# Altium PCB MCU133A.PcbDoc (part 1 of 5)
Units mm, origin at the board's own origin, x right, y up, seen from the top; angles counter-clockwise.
Board outline 58.42 x 139.7 mm, 4 copper layers (Top Signal, GND, PWR, Bottom Signal), stack 1.565 mm thick; 278 components, 226 nets, 1057 pads, 868 vias.
Unrouted connection lines stored in the file: 237.
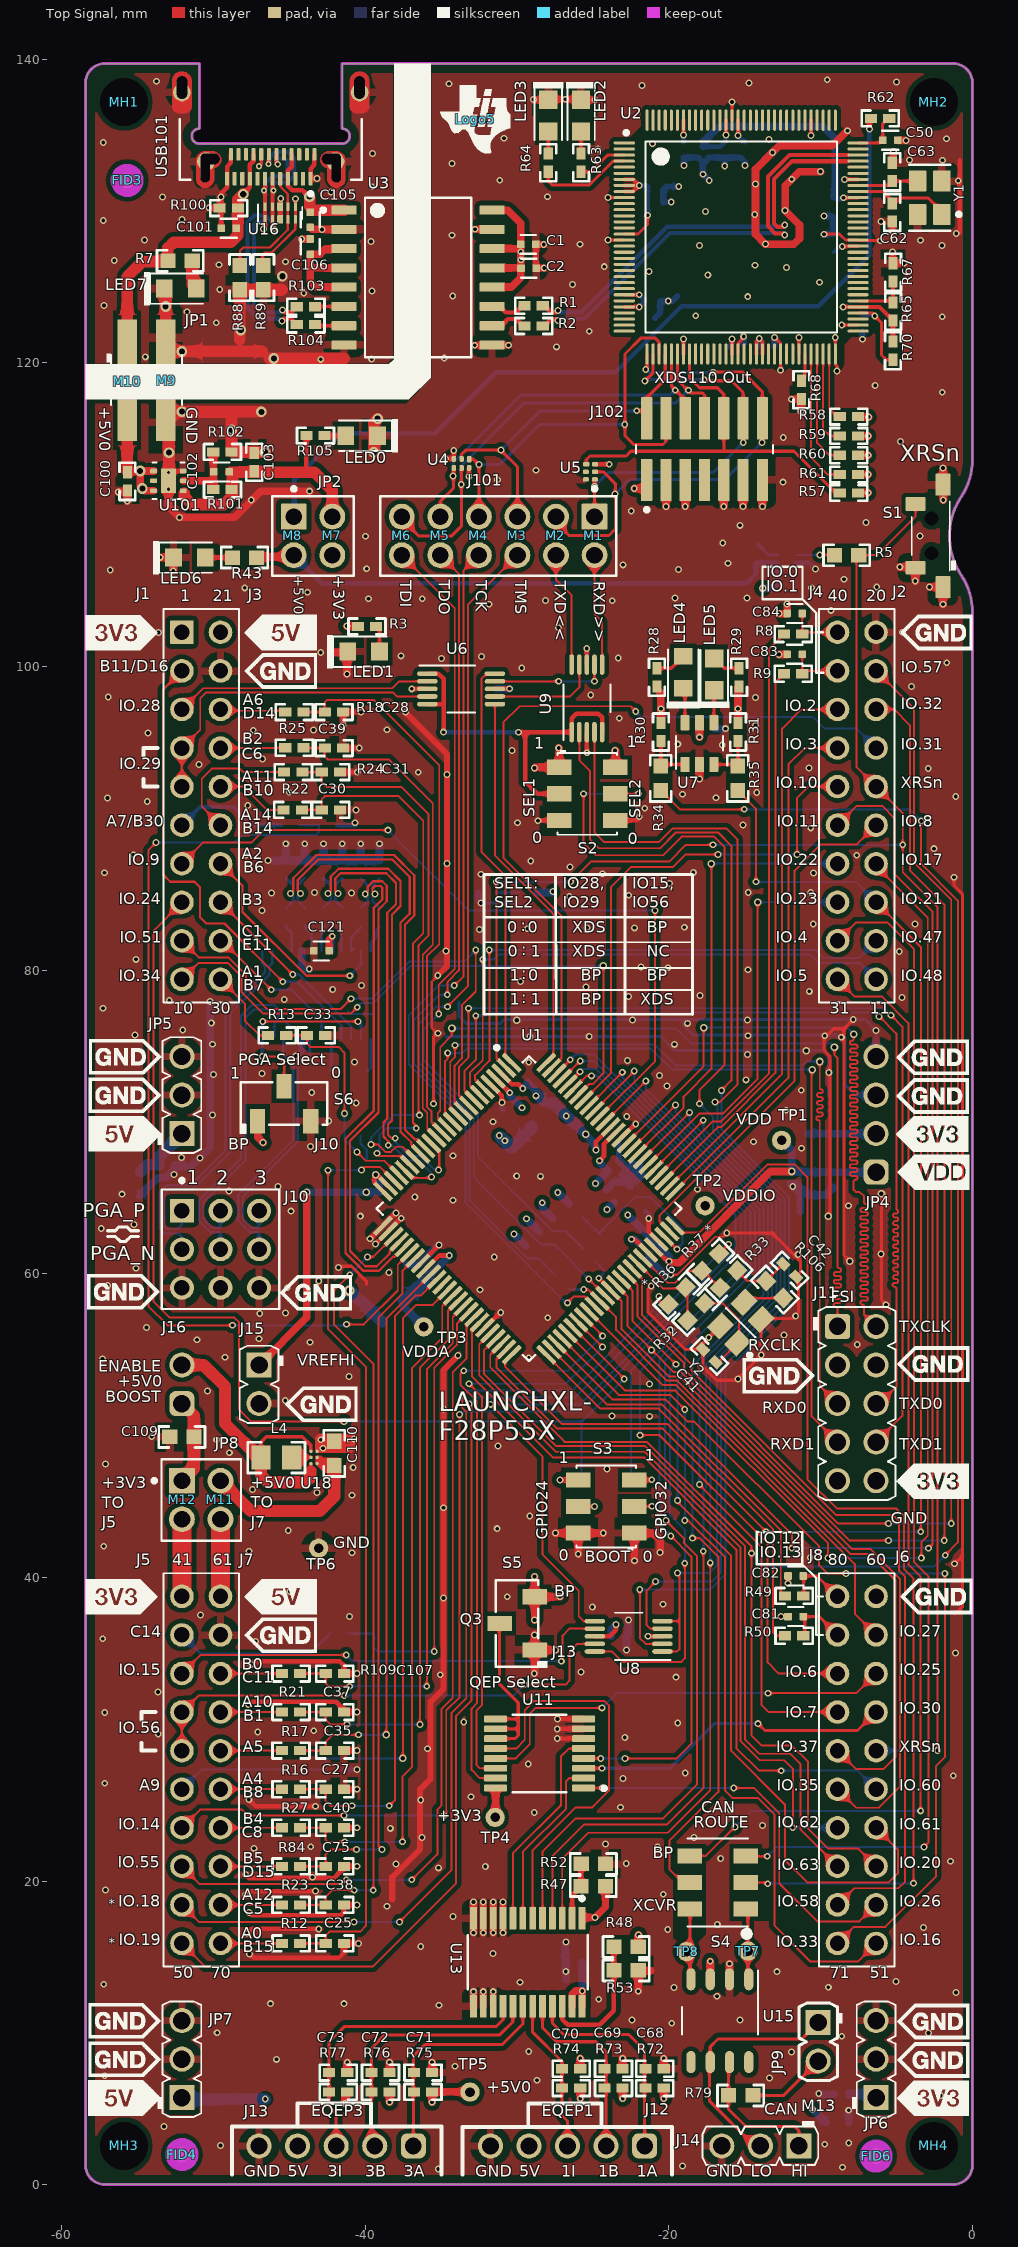
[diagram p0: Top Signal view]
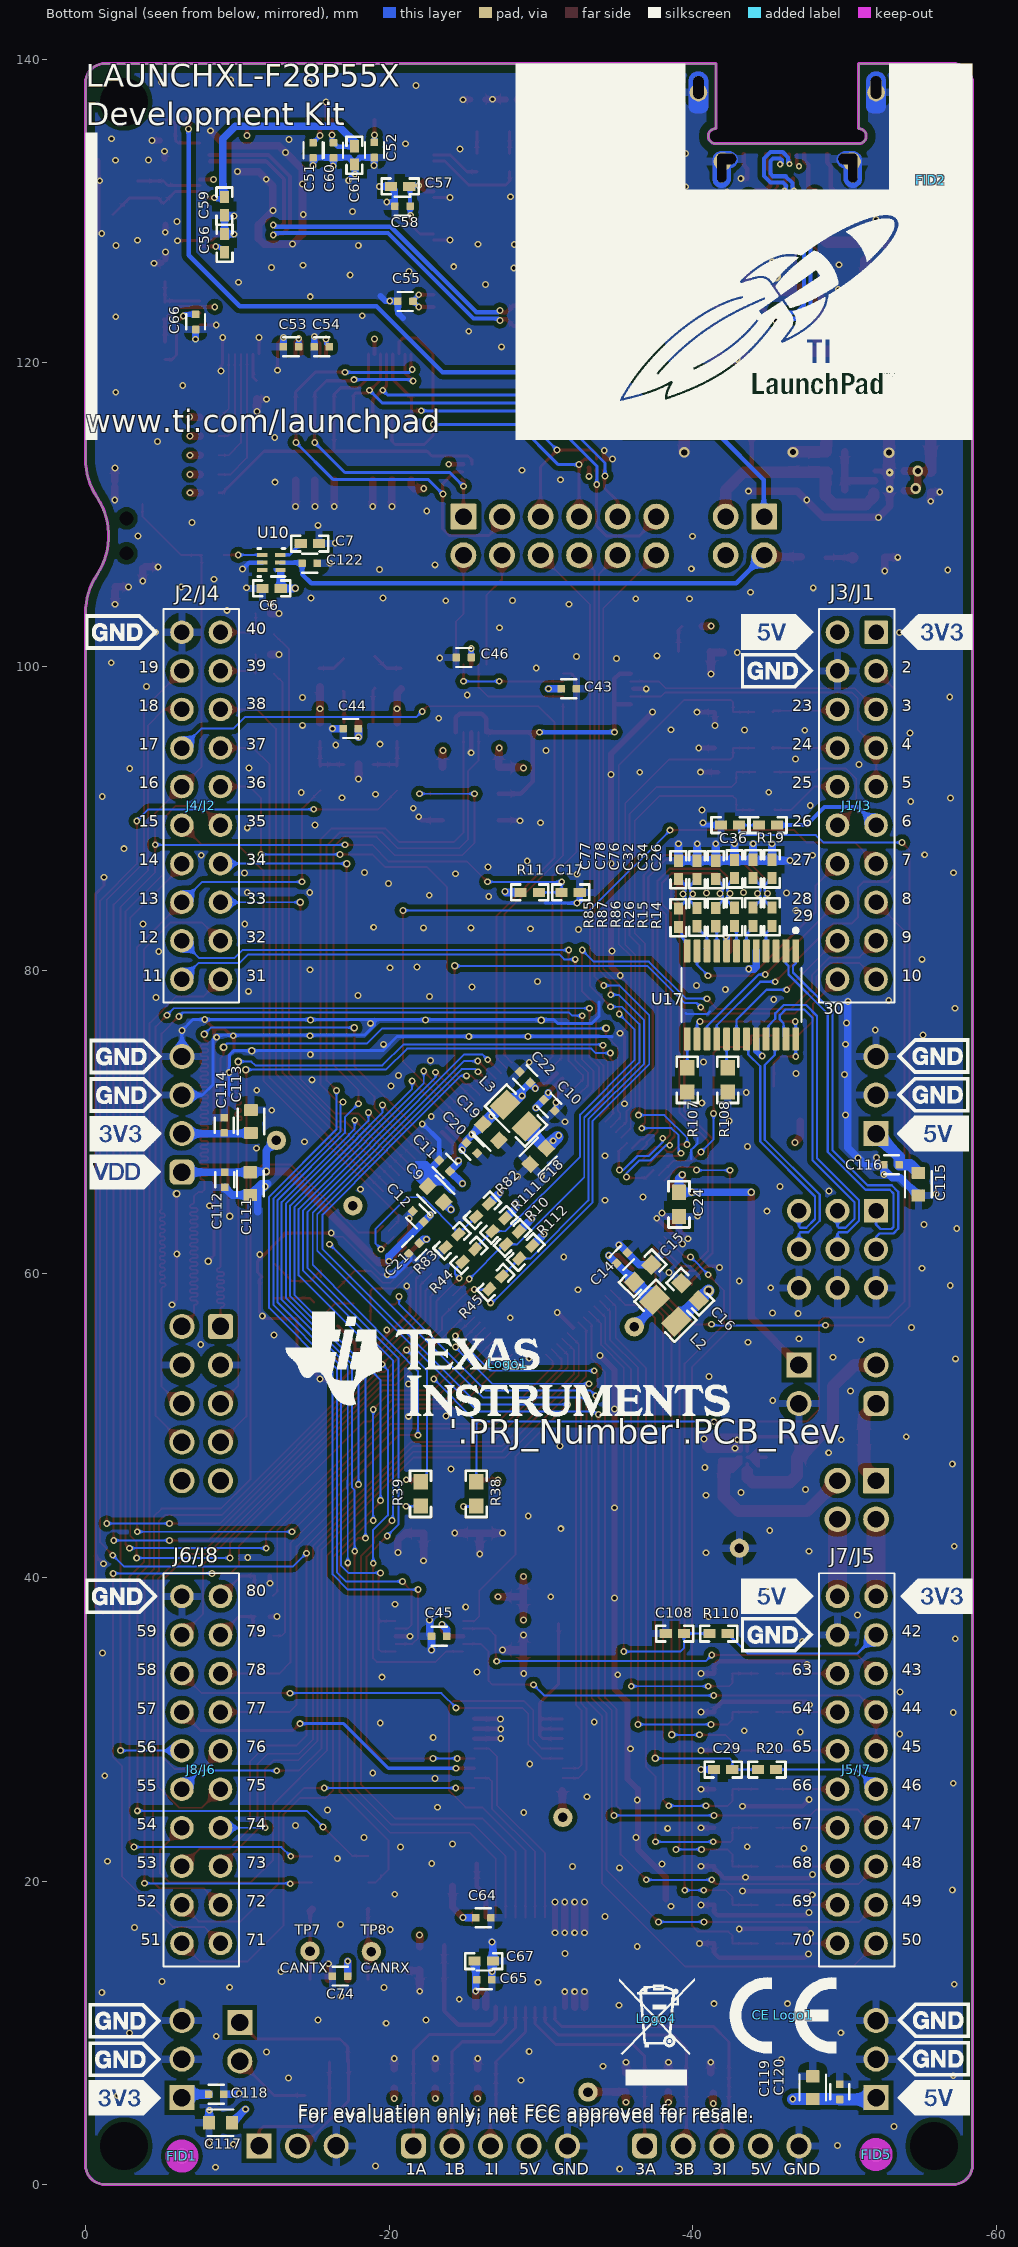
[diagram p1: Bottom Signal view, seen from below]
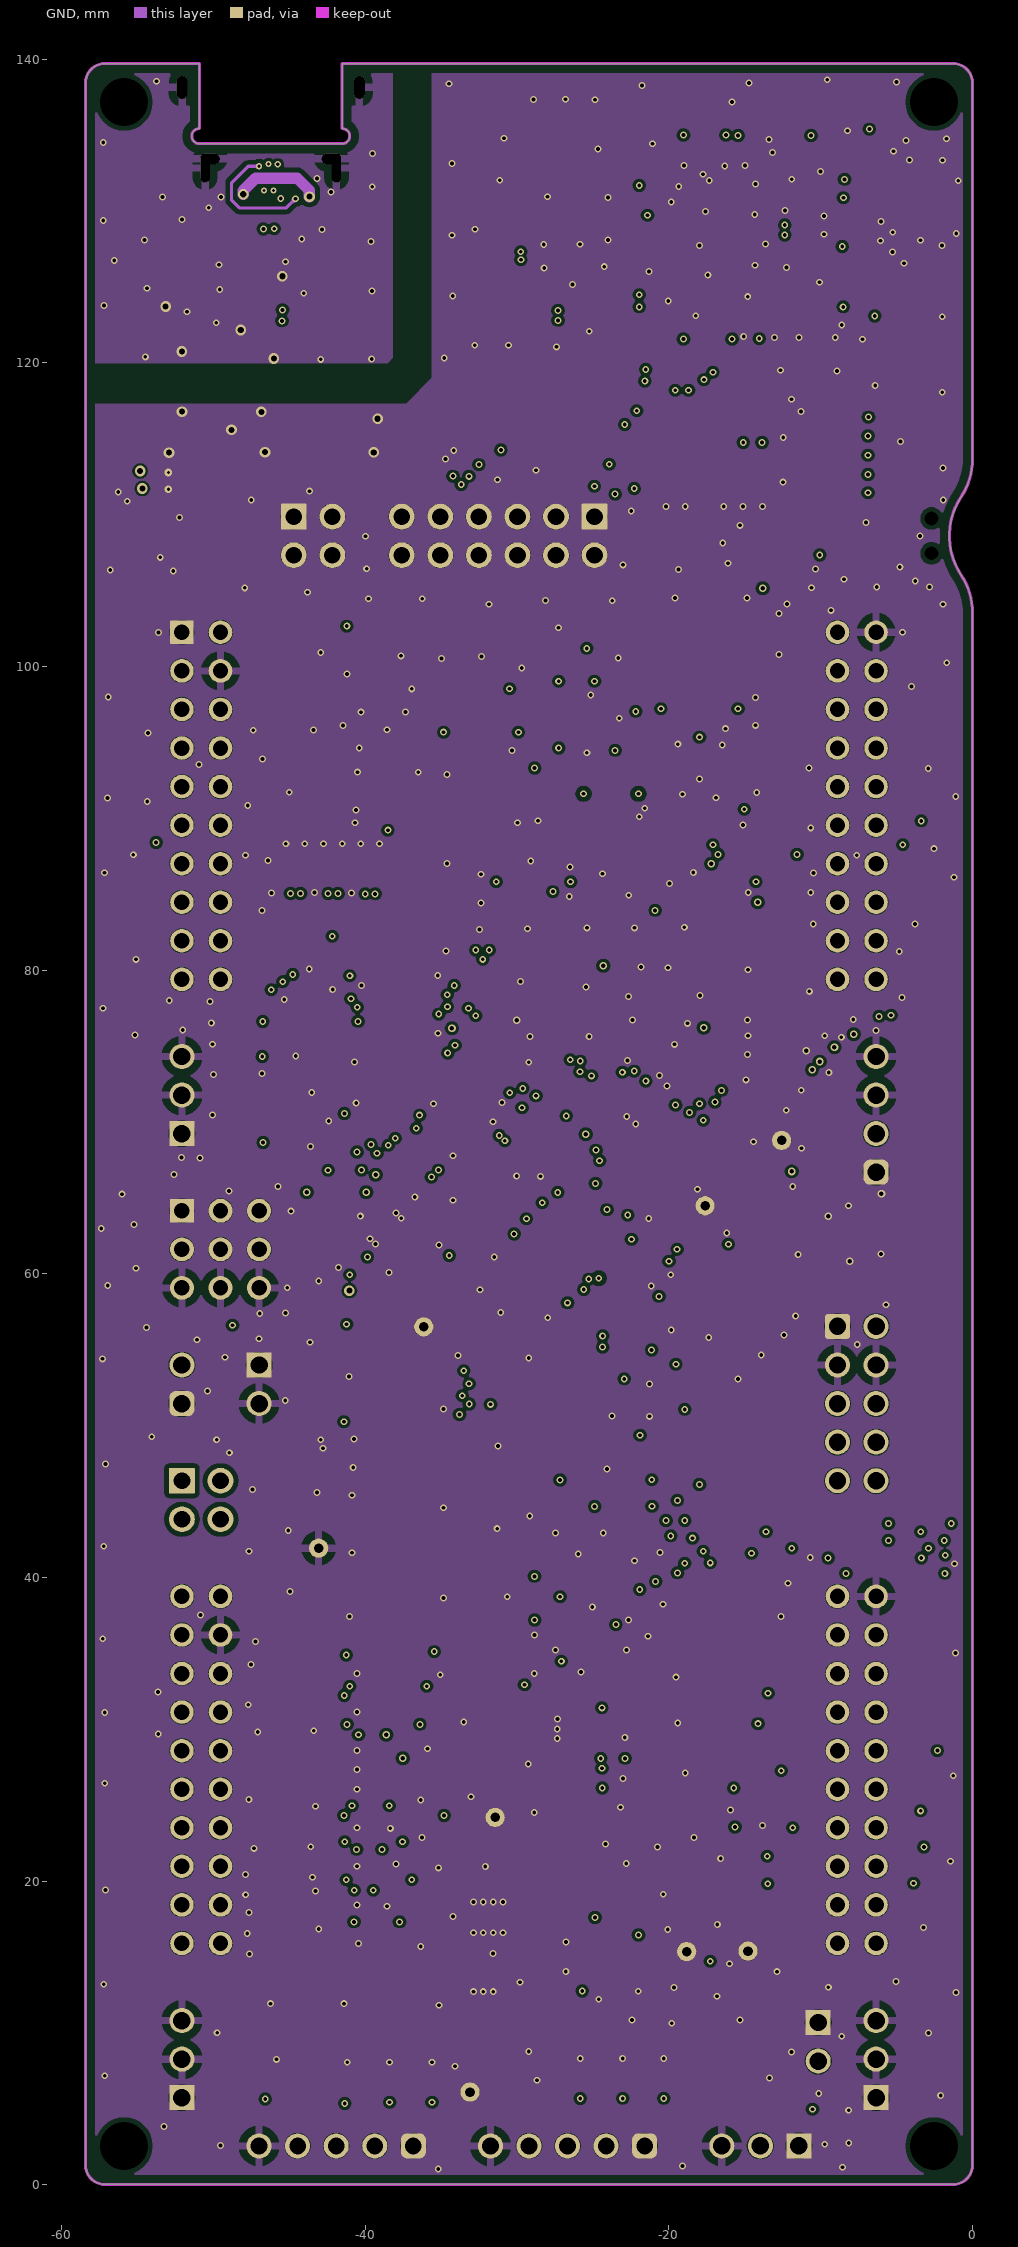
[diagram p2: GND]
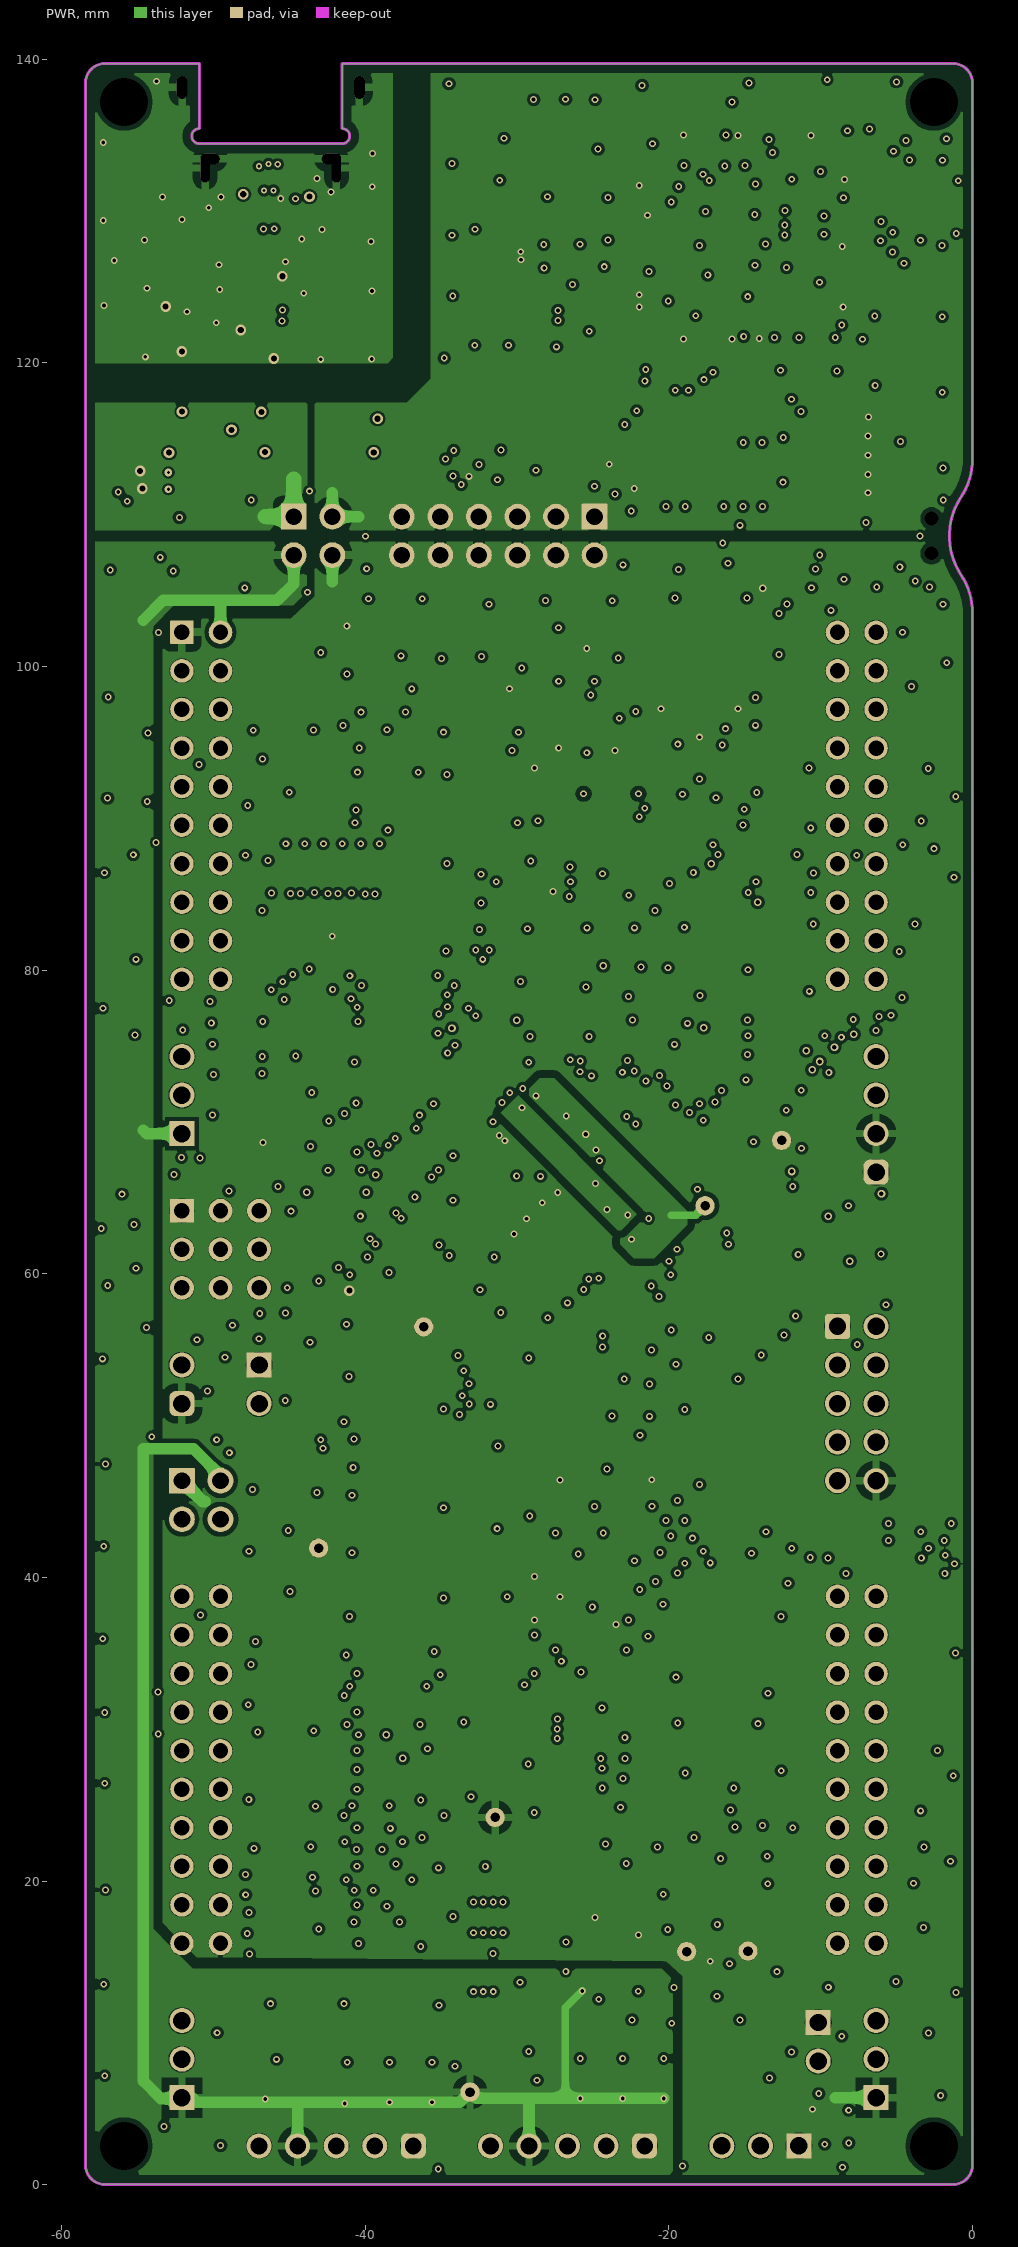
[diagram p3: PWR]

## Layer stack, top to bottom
Top Solder: solder mask 0.0102, Solder Resist, Dk 3.5
Top Signal: signal copper 0.0356
Dielectric 1: prepreg 0.2032, FR-4, Dk 4.2
GND: signal copper 0.0356
Dielectric 2: core 1.016, FR-4, Dk 4.2
PWR: signal copper 0.0356
Dielectric 3: prepreg 0.2032, FR-4, Dk 4.2
Bottom Signal: signal copper 0.0356
Bottom Solder: solder mask 0.0102, Solder Resist, Dk 3.5

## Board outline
-57.151,0.014 cw(c-57.151,1.284) -58.421,1.284 -58.421,138.444 cw(c-57.151,138.444) -57.151,139.714 -50.921,139.714 -50.921,135.434 ccw(c-50.921,134.934) -51.421,134.934 ccw(c-50.921,134.934) -50.921,134.434 -41.521,134.434 ccw(c-41.521,134.934) -41.021,134.934 ccw(c-41.521,134.934) -41.521,135.434 -41.521,139.714 -1.271,139.714 cw(c-1.271,138.444) -0.001,138.444 -0.001,113.679 cw(c-4.615,113.679) -0.763,111.139 ccw(c3.089,108.599) -0.763,106.059 cw(c-4.615,103.519) -0.001,103.519 -0.001,1.284 cw(c-1.271,1.284) -1.271,0.014

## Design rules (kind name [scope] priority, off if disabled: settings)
AcuteAngle [All] p1: minimum=4.50000000000000E+0001 checktracksonly=TRUE
AssemblyTestPointUsage [All] p1: valid=2
BoardOutlineClearance BoardOutlineClearance_MountingHoles [OnCopper and InComponentClass('Mounting Holes')] p1: gap=1.016 ignorepadtopadclearanceinfootprint=FALSE
BoardOutlineClearance BoardOutlineClearance_Poly [OnCopper and IsPoly] p2: gap=0.635 ignorepadtopadclearanceinfootprint=FALSE
BoardOutlineClearance BoardOutlineClearance_USB101 [InComponent('USB101')] p3: gap=0 ignorepadtopadclearanceinfootprint=FALSE
BoardOutlineClearance [OnCopper and Not InComponentClass('Logo') and not InComponentClass('FiducialMark') and not InRegion(1000,500,4000,800) and not InPoly] p4: gap=0.254 ignorepadtopadclearanceinfootprint=FALSE
Clearance USB101 [InComponent('USB101') vs OnLayer('Keep-Out Layer')] p1: gap=0.2 ignorepadtopadclearanceinfootprint=FALSE
Clearance Clearance_1 [inpolygon vs inpolygon] p2: gap=0.5 ignorepadtopadclearanceinfootprint=FALSE
Clearance ISVIA [ISVIA vs ISVIA] p3: gap=0.2 ignorepadtopadclearanceinfootprint=FALSE
Clearance Clearance_FiducialMark [InComponentClass('FiducialMark') vs InComponentClass('FiducialMark')] p4: gap=0 ignorepadtopadclearanceinfootprint=FALSE
Clearance Clearance_Boardedge [All vs IsKeepOut] p5: gap=0.3 ignorepadtopadclearanceinfootprint=FALSE
Clearance INPOLYGON [InPolygon] p6: gap=0.3 ignorepadtopadclearanceinfootprint=FALSE
Clearance [All] p7: gap=0.15 ignorepadtopadclearanceinfootprint=FALSE
ComponentClearance ComponentClearance_THtoTH_1 [All vs InComponentClass('Shunt')] p1: gap=0 collisioncheckmode=3 verticalgap=0 showdistances=FALSE
ComponentClearance "ComponentClearance_overlay to overlay" [OnBottomSilkscreen vs OnTopSilkscreen] p2: gap=0 collisioncheckmode=3 verticalgap=0 showdistances=FALSE
ComponentClearance ComponentClearance_MountingHoles_FiducialMarks [InComponentClass('Mounting Holes') vs InComponentClass('FiducialMark')] p3: gap=1.27 collisioncheckmode=3 verticalgap=0.254 showdistances=FALSE
ComponentClearance ComponentClearance_Shunt [InComponentClass('Header') vs InComponentClass('Shunt')] p4: gap=0 collisioncheckmode=3 verticalgap=0 showdistances=FALSE
ComponentClearance ComponentClearance_Logo [InComponentClass('Logo')] p5: gap=0 collisioncheckmode=3 verticalgap=0 showdistances=FALSE
ComponentClearance ComponentClearance_Logo_1 [InComponentClass('Logo') vs InComponentClass('Logo')] p6: gap=0 collisioncheckmode=3 verticalgap=0 showdistances=FALSE
ComponentClearance ComponentClearance_ScrewToNut [(HasFootprint('NY PMS 440 0025 PH')) vs (HasFootprint('Keystone_1902C'))] p7: gap=0.1 collisioncheckmode=3 verticalgap=0.1 showdistances=FALSE
ComponentClearance ComponentClearance_MountingHoles [InComponentClass('Mounting Holes')] p8: gap=6.35 collisioncheckmode=3 verticalgap=2540 showdistances=FALSE
ComponentClearance ComponentClearance_SmallPassives [HasFootprint('0201*') or HasFootprint('0402*') or HasFootprint('0508') or HasFootprint('0603*') or HasFootprint('0612') or HasFootprint('0805*') or HasFootprint('0815*') or HasFootprint('0830*') or HasFootprint('1206*') or HasFootprint('1210*') or HasFootprint('1808*') or HasFootprint('1812*') or HasFootprint('1825*') or HasFootprint('2010*') or HasFootprint('2220*') or HasFootprint('2225*') or HasFootprint('2512*') or HasFootprint('2728*') or HasFootprint('3518*') vs HasFootprint('0201*') or HasFootprint('0402*') or HasFootprint('0508') or HasFootprint('0603*') or HasFootprint('0612') or HasFootprint('0805*') or HasFootprint('0815*') or HasFootprint('0830*') or HasFootprint('1206*') or HasFootprint('1210*') or HasFootprint('1808*') or HasFootprint('1812*') or HasFootprint('1825*') or HasFootprint('2010*') or HasFootprint('2220*') or HasFootprint('2225*') or HasFootprint('2512*') or HasFootprint('2728*') or HasFootprint('3518*')] p9: gap=0.254 collisioncheckmode=3 verticalgap=0 showdistances=FALSE
ComponentClearance ComponentClearance_THtoSMT [IsThruComponent vs IsSMTComponent] p10: gap=0.254 collisioncheckmode=3 verticalgap=0.254 showdistances=FALSE
ComponentClearance ComponentClearance_THtoTH [IsThruComponent vs IsThruComponent] p11: gap=0.508 collisioncheckmode=3 verticalgap=0.762 showdistances=FALSE
DiffPairsRouting [All] p1: maxlimit=2.54 minlimit=0.15 mostfreqgap=0.15 toplayer_minwidth=0.15 toplayer_maxwidth=0.381 toplayer_prefwidth=0.27 midlayer1_minwidth=0.15 midlayer1_maxwidth=0.381 midlayer1_prefwidth=0.27 midlayer2_minwidth=0.15 midlayer2_maxwidth=0.381 midlayer2_prefwidth=0.27 bottomlayer_minwidth=0.15 bottomlayer_maxwidth=0.381 bottomlayer_prefwidth=0.27 maxuncoupledlength=25.4
FabricationTestPointUsage TestPointUsage [All] p1: valid=2 allowmultiple=FALSE
FabricationTestpoint Testpoint [All] p1: side=3 testpointundercomponent=TRUE minsize=1.016 maxsize=2.54 preferedsize=1.524 minholesize=0 maxholesize=1.016 preferedholesize=0.813 testpointgrid=0.025 allowsidetop=TRUE allowsidebottom=TRUE usegrid=TRUE gridtolerance=0
FanoutControl Fanout_LCC [IsLCC] p1: bgadir=Out bgaviamode=Centered fanoutstyle=Auto fanoutdirection=Alternating viagrid=0.025 // Fanout_LCC (Default Rule)
FanoutControl Fanout_BGA [IsBGA] p2: bgadir=Out bgaviamode=Centered fanoutstyle=Auto fanoutdirection=Alternating viagrid=0.025 // Fanout_BGA (Default Rule)
FanoutControl Fanout_Default [All] p4: bgadir=Out bgaviamode=Centered fanoutstyle=Auto fanoutdirection=Alternating viagrid=0.025 // Fanout_Default (Default Rule)
FanoutControl Fanout_Small [(CompPinCount < 5)] p5: bgadir=Out bgaviamode=Centered fanoutstyle=Auto fanoutdirection=OutThenIn viagrid=0.025 // Fanout_Small (Default Rule)
HoleSize [All] p1: absolutevalues=TRUE maxlimit=6.375 minlimit=0.2 maxpercent=80.000 minpercent=20.000
HoleToHoleClearance HoleToHoleClearance_USB101 [InComponent('USB101') vs InComponent('USB101')] p1: gap=0 allowstackedmicrovias=TRUE
HoleToHoleClearance [All] p2: gap=0.25 allowstackedmicrovias=TRUE
MatchedLengths FSIRX [InNetClass('FSIRX')] p1: tolerance=0.635 checknetsindiffpair=FALSE checkdiffpairvsdiffpair=TRUE checkxsignals=TRUE checkothers=TRUE
MatchedLengths FSITX [InNetClass('FSITX')] p2: tolerance=0.635 checknetsindiffpair=FALSE checkdiffpairvsdiffpair=TRUE checkxsignals=TRUE checkothers=TRUE
MinimumAnnularRing MinimumAnnularRing_1 [InComponent('USB101')] p1: minimumring=0
MinimumAnnularRing [All] p2: minimumring=0.1
MinimumAnnularRing MinimumAnnularRing_ThermalPadVias [IsVia and InAnyComponent] p3: minimumring=0.1
MinimumSolderMaskSliver MinimumSolderMaskSliver_Logo [InComponentClass('Logo') vs InComponentClass('Logo')] p1: minsoldermaskwidth=0.018
MinimumSolderMaskSliver [All] p2: minsoldermaskwidth=0.076
PlaneClearance [All] p1: clearance=0.127
PlaneConnect [All] p1: planeconnectstyle=Relief reliefexpansion=0.254 reliefentries=4 reliefconductorwidth=0.635 reliefairgap=0.254
PolygonConnect PolygonConnect_via [isvia] p1: connectstyle=Direct reliefconductorwidth=0.254 reliefentries=4 polygonreliefangle="90 Angle" airgapwidth=0.127
PolygonConnect [All] p2: connectstyle=Relief reliefconductorwidth=0.508 reliefentries=4 polygonreliefangle="90 Angle" airgapwidth=0.5
RoutingVias ThermalPadVias [IsVia and InAnyComponent] p1: holewidth=0.2 width=0.5 viastyle="Through Hole" minholewidth=0.2 minwidth=0.5 maxholewidth=0.33 maxwidth=0.6
RoutingVias [All] p2: holewidth=0.25 width=0.45 viastyle="Through Hole" minholewidth=0.2 minwidth=0.4 maxholewidth=1.016 maxwidth=1.651
SilkToBoardRegionClearance [Not ((IsComment or IsDesignator) And (Hide <> 'False')) and not InRegion(1000,500,4000,800)] p1:
SilkToSilkClearance SilkToSilkClearance_Pb-FreeLogo [(HasFootprint('Pb-Free_Overlay_Medium') OR HasFootprint('Pb-Free_Overlay_Small')) vs (HasFootprint('Pb-Free_Overlay_Medium') OR HasFootprint('Pb-Free_Overlay_Small'))] p1: silktosilkclearance=0
SilkToSilkClearance [All] p2: silktosilkclearance=0.076
SilkToSolderMaskClearance SilkToComponentPadClearance [(IsPad or IsFill or IsRegion) and InAnycomponent] p1: minsilkscreentomaskgap=0.076 clearancetoexposedcopper=TRUE
SilkToSolderMaskClearance "Silk to Solder Mask Opening" [(IsPad or IsFIll or IsRegion) and InAnyComponent] p2: minsilkscreentomaskgap=0.076 clearancetoexposedcopper=TRUE
SolderMaskExpansion SolderMaskExpansion_1 [All] p1: expansion=0.102 istentingtop=FALSE
SolderMaskExpansion SolderMaskExpansion_Via [IsVia] p2: expansion=0.051 istentingtop=FALSE
Width Analog [InNetClass('Analog')] p1: maxlimit=0.635 minlimit=0.203 preferedwidth=0.203
Width [All] p2: maxlimit=2.54 minlimit=0.127 preferedwidth=0.127 checkconnectedcopper=TRUE
13 further rules are at their usual default settings.

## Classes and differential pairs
component class MCU133A_F28P55x_Device: C9 C10 C11 C12 C14 C15 C16 C17 C18 C19 C20 C21 C22 L2 L3 R10 R11 R44 R45 R82 R83 R111 R112 S1
net class FSITX: GPIO44_FSITXCLK GPIO49_FSITXD0 GPIO50_FSITXD1
net class FSIRX: GPIO52_FSIRXD0 GPIO53_FSIRXD1 GPIO54_FSIRXCLK
component class MCU133A_USB_and_Power: C1 C2 C6 C7 C100 C101 C102 C103 C105 C106 C109 C110 C111 C112 C113 C114 C115 C116 C117 C118 C119 C120 C122 J16 JP1 JP2 JP4 JP5 JP6 JP7 JP10 L4 LED0 LED1 LED6 LED7 R1 R2 R3 R5 R7 R43 R88 R89 R100 R101 R102 R103 R104 R105 TP1 TP2 TP3 TP4 TP5 TP6 U3 U10 U16 U18 U101 USB101
component class MCU133A_XDS110_MCU: 45mil C50 C51 C52 C53 C54 C55 C56 C57 C58 C59 C60 C61 C62 C63 C66 J101 J102 LED2 LED3 R57 R58 R59 R60 R61 R62 R63 R64 R65 R67 R68 R70 R? U2 U4 U5 Y1
component class MCU133A_ADC: C24 C25 C26 C27 C28 C29 C30 C31 C32 C33 C34 C35 C36 C37 C38 C39 C40 C75 C76 C77 C78 C107 C108 J15 R12 R13 R14 R15 R16 R17 R18 R19 R20 R21 R22 R23 R24 R25 R26 R27 R84 R85 R86 R87 R109 R110 U1
component class MCU133A_Connectors: C68 C69 C70 C71 C72 C73 C74 C81 C82 C83 C84 J1/J3 J4/J2 J5/J7 J8/J6 J10 J11 J12 J13 J14 JP8 JP9 R8 R9 R49 R50 R72 R73 R74 R75 R76 R77 R79 TP7 TP8 U15
component class MCU133A_AltRouting_Misc: C41 C42 C43 C44 C45 C46 C64 C65 C67 C121 LED4 LED5 R28 R29 R30 R31 R32 R33 R34 R35 R36 R37 R38 R39 R47 R48 R52 R53 R106 R107 R108 S2 S3 S4 S5 S6 U6 U7 U8 U9 U11 U13 U17 Y2
component class Header: J11 J12 J13 J14 J15 J16 JP1 JP4 JP5 JP6 JP7 JP9 JP10
component class AssemblyNote: ZZ1 ZZ2 ZZ3
component class FiducialMark: FID1 FID2 FID3 FID4 FID5 FID6
component class MCU133A_Hardware: "CE Logo1" FID1 FID2 FID3 FID4 FID5 FID6 Logo1 Logo3 Logo4 Logo5 M1 M2 M3 M4 M5 M6 M7 M8 M9 M10 M11 M12 M13 MH1 MH2 MH3 MH4 ZZ1 ZZ2 ZZ3
component class Logo: Logo1 Logo5
component class Shunt: M1 M2 M3 M4 M5 M6 M7 M8 M9 M10 M11 M12 M13
differential pair XDS_D: +XDS_D_P -XDS_D_N
differential pair USB_D: +USB_D_P -USB_D_N
differential pair PGA3_IN: +PGA3_IN_P -PGA3_IN_N
differential pair PGA2_IN: +PGA2_IN_P -PGA2_IN_N
differential pair PGA1_IN: +PGA1_IN_P -PGA1_IN_N
differential pair MCU_PGA3_IN: +MCU_PGA3_IN_P -MCU_PGA3_IN_N
differential pair MCU_PGA2_IN: +MCU_PGA2_IN_P -MCU_PGA2_IN_N
differential pair MCU_PGA1_IN: +MCU_PGA1_IN_P -MCU_PGA1_IN_N
differential pair ADCINPGA3_IN: +ADCINPGA3_IN_P -ADCINPGA3_IN_N
differential pair ADCINPGA2_IN: +ADCINPGA2_IN_P -ADCINPGA2_IN_N
differential pair ADCINPGA1_IN: +ADCINPGA1_IN_P -ADCINPGA1_IN_N

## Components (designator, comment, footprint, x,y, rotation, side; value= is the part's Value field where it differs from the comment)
C1 "885012205018" FP-885012205018_0402-MFG -29.262,127.801 r180 top value=100nF
C2 "885012205018" FP-885012205018_0402-MFG -29.236,126.236 r180 top value=100nF
C6 "885012205037" 0402 -12.262,105.145 r0 bottom value=0.1uF
C7 "885012205037" 0402 -14.774,108.091 r180 bottom value=0.1uF
C9 "CC0603KRX5R6BB106" FP-CC0603KRX5R6BB106_0603-MFG -23.06,65.244 r225 bottom value=10µF
C10 "885012205018" FP-885012205018_0402-MFG -30.549,71.096 r45 bottom value=100nF
C11 "885012205018" FP-885012205018_0402-MFG -23.654,67.12 r225 bottom value=100nF
C12 "885012205018" FP-885012205018_0402-MFG -21.911,63.774 r225 bottom value=100nF
C14 "885012205018" FP-885012205018_0402-MFG -35.333,61.036 r315 bottom value=100nF
C15 "CGA3E3X5R1A225K080AB" 0603 -36.708,60.026 r135 bottom value=2.2uF
C16 "CGA3E3X5R1A225K080AB" 0603 -39.824,58.815 r45 bottom value=2.2uF
C17 "885012205037" 0402 -31.954,85.114 r180 bottom value=0.1uF
C18 "CC0603KRX5R6BB106" FP-CC0603KRX5R6BB106_0603-MFG -29.814,67.744 r135 bottom value=10µF
C19 "CC0603KRX5R6BB106" FP-CC0603KRX5R6BB106_0603-MFG -26.698,69.318 r45 bottom value=10µF
C20 "885012205018" FP-885012205018_0402-MFG -25.441,68.289 r45 bottom value=100nF
C21 "885012205018" FP-885012205018_0402-MFG -21.642,61.67 r135 bottom value=100nF
C22 "885012205018" FP-885012205018_0402-MFG -28.951,72.948 r225 bottom value=100nF
C24 "CGA3E3X5R1A225K080AB" 0603 -39.092,64.569 r270 bottom value=2.2uF
C25 "GRM1555C1H331JA01D" 0402 -42.003,15.889 r0 top value=330pF
C26 "GRM1555C1H331JA01D" 0402 -45.211,86.666 r90 bottom value=330pF
C27 "GRM1555C1H331JA01D" 0402 -42.003,26.049 r0 top value=330pF
C28 "GRM1555C1H331JA01D" 0402 -42.054,96.999 r0 top value=330pF
C29 "GRM1555C1H331JA01D" 0402 -42.003,27.344 r0 bottom value=330pF
C30 "GRM1555C1H331JA01D" 0402 -42.261,90.549 r0 top value=330pF
C31 "GRM1555C1H331JA01D" 0402 -42.261,93.039 r0 top value=330pF
C32 "GRM1555C1H331JA01D" 0402 -42.755,86.664 r90 bottom value=330pF
C33 "GRM1555C1H331JA01D" 0402 -43.232,75.698 r0 top value=330pF
C34 "GRM1555C1H331JA01D" 0402 -43.976,86.668 r90 bottom value=330pF
C35 "GRM1555C1H331JA01D" 0402 -42.003,28.589 r0 top value=330pF
C36 "GRM1555C1H331JA01D" 0402 -42.454,89.549 r0 bottom value=330pF
C37 "GRM1555C1H331JA01D" 0402 -42.003,31.129 r0 top value=330pF
C38 "GRM1555C1H331JA01D" 0402 -42.003,18.429 r0 top value=330pF
C39 "GRM1555C1H331JA01D" 0402 -42.056,94.629 r0 top value=330pF
C40 "GRM1555C1H331JA01D" 0402 -42.003,23.509 r0 top value=330pF
C41 "C0402C120J3GACAUTO" 0402 -17.333,54.596 r135 top value=12pF
C42 "C0402C120J3GACAUTO" 0402 -12.041,60.224 r315 top value=12pF
C43 "885012205018" FP-885012205018_0402-MFG -31.836,98.535 r180 bottom value=100nF
C44 "885012205018" FP-885012205018_0402-MFG -17.476,95.911 r180 bottom value=100nF
C45 "885012205018" FP-885012205018_0402-MFG -23.286,36.121 r0 bottom value=100nF
C46 "885012205018" FP-885012205018_0402-MFG -24.907,100.591 r180 bottom value=100nF
C50 "885012205050" FP-885012205050_0402-MFG -5.414,134.665 r180 top value=10nF
C51 "885012205050" FP-885012205050_0402-MFG -14.987,133.999 r90 bottom value=10nF
C52 "885012205050" FP-885012205050_0402-MFG -19.031,134.022 r90 bottom value=10nF
C53 "885012205050" FP-885012205050_0402-MFG -13.532,121.052 r180 bottom value=10nF
C54 "885012205018" FP-885012205018_0402-MFG -15.562,121.052 r180 bottom value=100nF
C55 "885012205018" FP-885012205018_0402-MFG -21.072,124.045 r180 bottom value=100nF
C56 "885012105012" 0402 -9.165,127.881 r90 bottom value=1uF
C57 "885012105012" 0402 -20.728,131.622 r0 bottom value=1uF
C58 "885012205050" FP-885012205050_0402-MFG -20.88,130.316 r180 bottom value=10nF
C59 "885012105012" 0402 -9.144,130.323 r270 bottom value=1uF
C60 "885012205018" FP-885012205018_0402-MFG -16.337,133.997 r90 bottom value=100nF
C61 "885012105012" 0402 -17.715,133.667 r270 bottom value=1uF
C62 "CL05C120JB5NNNC" 0402 -5.282,129.9 r270 top value=12pF
C63 "CL05C120JB5NNNC" 0402 -5.282,132.576 r90 top value=12pF
C64 "885012205018" FP-885012205018_0402-MFG -26.2,17.578 r180 bottom value=100nF
C65 "885012205018" FP-885012205018_0402-MFG -26.271,13.489 r0 bottom value=100nF
C66 "885012205018" FP-885012205018_0402-MFG -7.252,122.697 r90 bottom value=100nF
C67 "885012205061" 0402 -26.229,14.725 r180 bottom value=1000pF
C68 "885012205061" 0402 -20.931,7.634 r0 top value=1000pF
C69 "885012205061" 0402 -23.642,7.634 r0 top value=1000pF
C70 "885012205061" 0402 -26.436,7.634 r0 top value=1000pF
C71 "885012205061" 0402 -36.196,7.38 r0 top value=1000pF
C72 "885012205061" 0402 -38.99,7.38 r0 top value=1000pF
C73 "885012205061" 0402 -41.784,7.38 r0 top value=1000pF
C74 "885012205018" FP-885012205018_0402-MFG -16.765,13.738 r0 bottom value=100nF
C75 "GRM1555C1H331JA01D" 0402 -42.003,20.969 r0 top value=330pF
C76 "GRM1555C1H331JA01D" 0402 -41.512,86.605 r90 bottom value=330pF
C77 "GRM1555C1H331JA01D" 0402 -39.057,86.605 r90 bottom value=330pF
C78 "GRM1555C1H331JA01D" 0402 -40.289,86.605 r90 bottom value=330pF
C81 "885012205018" FP-885012205018_0402-MFG -11.649,37.419 r0 top value=100nF
C82 "885012205018" FP-885012205018_0402-MFG -11.648,40.094 r0 top value=100nF
C83 "885012205018" FP-885012205018_0402-MFG -11.71,100.798 r0 top value=100nF
C84 "885012205018" FP-885012205018_0402-MFG -11.71,103.492 r0 top value=100nF
C100 "885012105012" 0402 -55.659,112.19 r270 top value=1uF
C101 "885012205064" FP-885012205064_0402-MFG -48.99,128.863 r0 top value=3.3nF
C102 "885012205050" FP-885012205050_0402-MFG -49.463,112.814 r0 top value=10nF
C103 "885012105012" 0402 -47.311,113.46 r90 top value=1uF
C105 "885012205018" FP-885012205018_0402-MFG -43.627,129.427 r90 top value=100nF
C106 "885012205018" FP-885012205018_0402-MFG -43.627,127.657 r270 top value=100nF
C107 "GRM1555C1H331JA01D" 0402 -42.003,33.669 r0 top value=330pF
C108 "GRM1555C1H331JA01D" 0402 -38.815,36.304 r0 bottom value=330pF
C109 "885012106018" 0603 -52.075,49.254 r180 top value=2.2uF
C110 "GRM188R61C106KAALD" 0603 -42.037,48.165 r90 top value=10uF
C111 "CC0603KRX5R6BB106" FP-CC0603KRX5R6BB106_0603-MFG -10.859,65.936 r90 bottom value=10µF
C112 "885012205018" FP-885012205018_0402-MFG -9.17,66.189 r90 bottom value=100nF
C113 "CC0603KRX5R6BB106" FP-CC0603KRX5R6BB106_0603-MFG -10.898,70.029 r270 bottom value=10µF
C114 "885012205018" FP-885012205018_0402-MFG -9.135,69.775 r90 bottom value=100nF
C115 "CC0603KRX5R6BB106" FP-CC0603KRX5R6BB106_0603-MFG -54.858,65.897 r90 bottom value=10µF
C116 "885012205018" FP-885012205018_0402-MFG -53.087,67.172 r0 bottom value=100nF
C117 "CC0603KRX5R6BB106" FP-CC0603KRX5R6BB106_0603-MFG -8.891,4.078 r180 bottom value=10µF
C118 "885012205018" FP-885012205018_0402-MFG -8.611,5.958 r180 bottom value=100nF
C119 "CC0603KRX5R6BB106" FP-CC0603KRX5R6BB106_0603-MFG -47.905,6.389 r270 bottom value=10µF
C120 "885012205018" FP-885012205018_0402-MFG -49.683,6.11 r90 bottom value=100nF
C121 "885012205018" FP-885012205018_0402-MFG -42.881,81.263 r180 top value=100nF
C122 "885012205018" FP-885012205018_0402-MFG -14.763,106.796 r180 bottom value=100nF
"CE Logo1" "CE Mark" CE_Mark_5mm -45.937,11.152 r180 bottom
FID1 "Fiducial" Fiducial10-20 -6.351,1.886 r180 bottom
FID2 "Fiducial" Fiducial10-20 -55.681,132.015 r180 bottom
FID3 "Fiducial" Fiducial10-20 -55.681,132.015 r0 top
FID4 "Fiducial" Fiducial10-20 -52.071,1.987 r0 top
FID5 "Fiducial" Fiducial10-20 -52.071,1.987 r180 bottom
FID6 "Fiducial" Fiducial10-20 -6.351,1.886 r0 top
J1/J3 "SSQ-110-03-T-D" BoosterPack_40pin_J1J3 -50.801,90.819 r180 bottom locked
J4/J2 "SSQ-110-03-T-D" BoosterPack_40pin_J2J4 -7.621,90.819 r180 bottom locked
J5/J7 "SSQ-110-03-T-D" BoosterPack_40pin_J5J7 -50.801,27.319 r180 bottom locked
J8/J6 "SSQ-110-03-T-D" BoosterPack_40pin_J6J8 -7.621,27.319 r180 bottom locked
J10 "TSW-103-07-G-T" FP-TSW-103-07-G-T_HDR9-MFG -49.531,61.609 r270 top locked
J11 "61301021121" WURTH_61301021121 -7.621,51.449 r270 top locked
J12 "61300511121" Wurth_61300511121 -26.671,2.554 r180 top locked
J13 "61300511121" Wurth_61300511121 -41.911,2.554 r180 top locked
J14 "61300311121" WURTH_61300311121 -13.971,2.554 r180 top locked
J15 "61300211121" WURTH_61300211121#1 -46.991,52.719 r270 top locked
J16 "61300211121" WURTH_61300211121#2 -52.071,52.719 r90 top locked
J101 "61301221121" FP-61301221121_HDR12-MFG -31.243,108.599 r180 top locked
J102 "FTSH-107-01-F-DV-K" FP-FTSH-107-01-F-DV-K_HDR14-MFG -17.649,114.314 r0 top
JP1 "TSM-102-01-L-DV" Samtec_TSM-102-01-x-DV -54.407,118.861 r270 top locked
JP2 "61300421121" FP-61300421121_HDR4-MFG#1 -43.435,108.599 r0 top
JP4 "61300411121" WURTH_61300411121 -6.351,70.499 r90 top locked
JP5 "61300311121" WURTH_61300311121 -52.071,71.769 r90 top locked
JP6 "61300311121" WURTH_61300311121 -6.351,8.269 r90 top locked
JP7 "61300311121" WURTH_61300311121 -52.071,8.269 r90 top locked
JP8 "61300421121" FP-61300421121_HDR4-MFG#2 -50.801,45.099 r270 top locked
JP9 "61300211121" WURTH_61300211121#1 -10.161,9.412 r270 top
L2 "742792063" 0805_HV -38.193,57.563 r45 bottom value="60 ohm"
L3 "742792022" 0805_HV -28.347,70.423 r45 bottom value="220 ohm"
L4 "LQM21PN1R0MC0D" 0805_HV -45.848,47.893 r0 top value=1uH
LED0 "150080SS75000" WL-SMCW_RED_0805 -40.235,115.203 r180 top value=Red
LED1 "150080SS75000" WL-SMCW_RED_0805 -40.107,100.979 r0 top value=Red
LED2 "LTST-C170TBKT" LTST-C170TBKT_Blue -25.782,136.285 r90 top value=Blue
LED3 "LTST-C170TBKT" LTST-C170TBKT_Blue -27.941,136.285 r90 top value=Blue
LED4 "150080SS75000" WL-SMCW_RED_0805 -19.051,99.616 r90 top value=Red
LED5 "LTST-C171GKT" LED_LTST-C171 -17.003,99.478 r270 top value=Green
LED6 "150080SS75000" WL-SMCW_RED_0805 -51.576,107.171 r0 top value=Red
LED7 "150080SS75000" WL-SMCW_RED_0805 -52.185,124.89 r0 top value=Red
Logo1 "Texas Instruments" TI_Stacked_Overlay_Medium -27.804,54.069 r180 bottom
Logo3 "FCC disclaimer" FCC_disclaimer 25.272,4.078 r180 bottom
Logo4 "WEEE logo" WEEE_Minimum -37.593,10.936 r180 bottom
Logo5 "Texas Instruments" TI_Symbol_Overlay_Small -32.746,136.031 r0 top
M1 "60900213421" Wurth_60900213421 -24.948,108.599 r270 top
M2 "60900213421" Wurth_60900213421 -27.442,108.599 r90 top
M3 "60900213421" Wurth_60900213421 -29.973,108.599 r90 top
M4 "60900213421" Wurth_60900213421 -32.513,108.599 r90 top
M5 "60900213421" Wurth_60900213421 -35.053,108.599 r90 top
M6 "60900213421" Wurth_60900213421 -37.593,108.599 r90 top
M7 "60900213421" Wurth_60900213421 -42.165,108.599 r90 top
M8 "60900213421" Wurth_60900213421 -44.788,108.599 r90 top
M9 "60900213421" Wurth_60900213421 -53.086,118.806 r90 top
M10 "60900213421" Wurth_60900213421 -55.675,118.759 r90 top
M11 "60900213421" Wurth_60900213421 -49.531,45.099 r90 top
M12 "60900213421" Wurth_60900213421 -52.061,45.099 r90 top
M13 "60900213421" Wurth_60900213421 -10.138,9.445 r90 top
MH1 "MTG_NoPads" NPTH125mil -55.881,137.174 r0 top
MH2 "MTG_NoPads" NPTH125mil -2.541,137.174 r0 top
MH3 "MTG_NoPads" NPTH125mil -55.881,2.554 r0 top
MH4 "MTG_NoPads" NPTH125mil -2.541,2.554 r0 top locked
R1 "RC0402JR-070RL" 0402 -28.903,123.759 r0 top value=0
R2 "RC0402JR-070RL" 0402 -28.903,122.426 r0 top value=0
R3 "CRCW0402680RJNED" 0402 -39.885,102.645 r180 top value=680
R5 "ERJ-3GEY0R00V" 0603 -8.286,107.329 r180 top value=0
R7 "RC0603JR-073KL" 0603 -52.193,126.718 r180 top value=3.0k
R8 "RC0402JR-070RL" 0402 -11.813,102.134 r0 top value=0
R9 "RC0402JR-070RL" 0402 -11.813,99.524 r0 top value=0
R10 "CRCW04022K20JNED" 0402 -28.123,62.357 r135 bottom value=2.2k
R11 "CRCW04022K20JNED" 0402 -29.26,85.114 r0 bottom value=2.2k
R12 "RC0402JR-070RL" 0402 -44.89,15.889 r0 top value=0
R13 "RC0402JR-070RL" 0402 -45.802,75.698 r0 top value=0
R14 "RC0402JR-070RL" 0402 -45.206,83.515 r90 bottom value=0
R15 "RC0402JR-070RL" 0402 -43.974,83.515 r90 bottom value=0
R16 "RC0402JR-070RL" 0402 -44.89,26.049 r0 top value=0
R17 "RC0402JR-070RL" 0402 -44.89,28.589 r0 top value=0
R18 "RC0402JR-070RL" 0402 -44.67,96.999 r0 top value=0
R19 "RC0402JR-070RL" 0402 -44.954,89.549 r0 bottom value=0
R20 "RC0402JR-070RL" 0402 -44.89,27.344 r0 bottom value=0
R21 "RC0402JR-070RL" 0402 -44.89,31.129 r0 top value=0
R22 "RC0402JR-070RL" 0402 -44.771,90.549 r0 top value=0
R23 "RC0402JR-070RL" 0402 -44.89,18.429 r0 top value=0
R24 "RC0402JR-070RL" 0402 -44.737,93.039 r0 top value=0
R25 "RC0402JR-070RL" 0402 -44.664,94.645 r0 top value=0
R26 "RC0402JR-070RL" 0402 -42.734,83.508 r90 bottom value=0
R27 "RC0402JR-070RL" 0402 -44.89,23.509 r0 top value=0
R28 "CRCW0402680RJNED" 0402 -20.782,99.285 r270 top value=680
R29 "CRCW0402680RJNED" 0402 -15.368,99.285 r270 top value=680
R30 "CRCW040210M0JNED" 0402 -20.523,95.684 r90 top value=10Meg
R31 "CRCW040210M0JNED" 0402 -15.443,95.684 r90 top value=10Meg
R32 "CRCW06030000Z0EA" 0603 -18.208,57.486 r45 top value=0
R33 "CRCW06030000Z0EA" 0603 -16.067,59.644 r45 top value=0
R34 "CRCW06030000Z0EA" 0603 -20.523,92.636 r90 top value=0
R35 "CRCW06030000Z0EA" 0603 -15.469,92.636 r90 top value=0
R36 "CRCW06030000Z0EA" 0603 -19.453,58.546 r45 top value=0
R37 "CRCW06030000Z0EA" 0603 -17.259,60.759 r225 top value=0
R38 "RC0603FR-0710KL" 0603 -25.744,45.497 r270 bottom value=10.0k
R39 "RC0603FR-0710KL" 0603 -22.068,45.497 r90 bottom value=10.0k
R43 "RC0603JR-073KL" 0603 -47.95,107.171 r0 top value=3.0k
R44 "RC0402JR-070RL" 0402 -25.252,61.206 r135 bottom value=0
R45 "RC0402JR-070RL" 0402 -27.018,59.411 r135 bottom value=0
R47 "CRCW06030000Z0EA" 0603 -24.979,19.667 r0 top value=0
R48 "CRCW06032K20JNEA" 0603 -22.817,15.659 r0 top value=2.2k
R49 "RC0402JR-070RL" 0402 -11.749,38.781 r0 top value=0
R50 "RC0402JR-070RL" 0402 -11.749,36.157 r0 top value=0
R52 "CRCW06030000Z0EA" 0603 -24.966,21.128 r180 top value=0
R53 "CRCW06030000Z0EA" 0603 -22.817,14.111 r0 top value=0
R57 "CRCW04023K30JNED" 0402 -8.143,111.438 r0 top value=3.3k
R58 "CRCW04021K00FKED" 0402 -8.147,116.452 r0 top value=1.00k
R59 "CRCW04021K00FKED" 0402 -8.147,115.182 r0 top value=1.00k
R60 "CRCW04021K00FKED" 0402 -8.147,113.912 r0 top value=1.00k
R61 "CRCW04021K00FKED" 0402 -8.147,112.642 r0 top value=1.00k
R62 "CRCW0402100RJNED" 0402 -6.079,136.105 r0 top value=100
R63 "RC0402FR-07470RL" 0402 -25.782,133.186 r270 top value=470
R64 "RC0402FR-07470RL" 0402 -27.941,133.186 r270 top value=470
R65 "CRCW040210K0JNED" 0402 -5.233,123.384 r270 top value=10k
R67 "CRCW040210K0JNED" 0402 -5.233,125.963 r270 top value=10k
R68 "CRCW04024K87FKED" 0402 -11.263,118.223 r90 top value=4.87k
R70 "CRCW040251R0JNED" 0402 -5.242,120.806 r90 top value=51
R72 "CRCW04021K00FKED" 0402 -20.931,6.364 r0 top value=1.00k
R73 "CRCW04021K00FKED" 0402 -23.642,6.364 r0 top value=1.00k
R74 "CRCW04021K00FKED" 0402 -26.436,6.364 r0 top value=1.00k
R75 "CRCW04021K00FKED" 0402 -36.196,6.11 r0 top value=1.00k
R76 "CRCW04021K00FKED" 0402 -38.99,6.11 r0 top value=1.00k
R77 "CRCW04021K00FKED" 0402 -41.784,6.11 r0 top value=1.00k
R79 "RC0603FR-07120RL" 0603 -15.266,5.881 r180 top value=120
R82 "ERJ-2GE0R00X" 0402 -26.143,64.184 r315 bottom value=0
R83 "ERJ-2GE0R00X" 0402 -24.136,62.172 r315 bottom value=0
R84 "RC0402JR-070RL" 0402 -44.89,20.969 r0 top value=0
R85 "RC0402JR-070RL" 0402 -39.057,83.449 r90 bottom value=0
R86 "RC0402JR-070RL" 0402 -41.512,83.485 r90 bottom value=0
R87 "RC0402JR-070RL" 0402 -40.289,83.485 r90 bottom value=0
R88 "RC0603JR-075K1L" 0603 -48.251,125.614 r90 top value=5.1k
R89 "RC0603JR-075K1L" 0603 -46.703,125.614 r90 top value=5.1k
R100 "CRCW04021M00FKED" 0402 -48.988,130.189 r0 top value=1.00Meg
R101 "CRCW040252K3FKED" 0402 -49.404,111.647 r0 top value=52.3k
R102 "CRCW040230K0FKED" 0402 -49.404,114.136 r180 top value=30.0k
R103 "RC0402JR-070RL" 0402 -43.906,123.692 r0 top value=0
R104 "RC0402JR-070RL" 0402 -43.906,122.515 r0 top value=0
R105 "CRCW0402680RJNED" 0402 -43.273,115.203 r180 top value=680
R106 "FC0603E50R0BTBST1" 0603 -13.025,58.962 r135 top value=50
R107 "CRCW06030000Z0EA" 0603 -39.631,72.769 r270 bottom value=0
R108 "CRCW06030000Z0EA" 0603 -42.296,72.769 r270 bottom value=0
R109 "RC0402JR-070RL" 0402 -44.89,33.669 r0 top value=0
R110 "RC0402JR-070RL" 0402 -41.702,36.304 r0 bottom value=0
R111 "RC0402JR-070RL" 0402 -27.222,63.226 r135 bottom value=0
R112 "RC0402JR-070RL" 0402 -28.997,61.422 r135 bottom value=0
S1 "1188E-1K2-V-TR" SW_1188E -3.049,108.599 r180 top
S2 "CAS-D20TA" SW_CAS-D20TA -25.374,91.615 r0 top
S3 "CAS-D20TA" SW_CAS-D20TA -24.124,44.666 r180 top
S4 "CAS-220TA" SW_CAS-220TA -16.782,19.903 r180 top locked
S5 "CAS-120TA" SW_CAS-120TA -29.99,36.972 r180 top
S6 "CAS-120TA" SW_CAS-120TA -45.34,71.203 r90 top
TP1 "TESTPOINT" TP_50MIL-25MILHOLE -12.574,68.785 r0 top
TP2 "TESTPOINT" TP_50MIL-25MILHOLE -17.611,64.479 r0 top
TP3 "TESTPOINT" TP_50MIL-25MILHOLE -36.146,56.504 r0 top
TP4 "TESTPOINT" TP_50MIL-25MILHOLE -31.441,24.191 r0 top
TP5 "TESTPOINT" TP_50MIL-25MILHOLE -33.097,6.1 r0 top
TP6 "TESTPOINT" TP_50MIL-25MILHOLE -43.067,41.924 r0 top
TP7 "TESTPOINT" TP_50MIL-25MILHOLE -14.784,15.381 r90 top
TP8 "TESTPOINT" TP_50MIL-25MILHOLE -18.827,15.352 r90 top
U1 "TMS320F28P550SJ9PZ" PZ0100A-MFG -29.211,64.29 r315 top locked
U2 "MSP432E401YTPDT" PDT0128A -15.236,128.284 r0 top locked
U3 "ISOUSB111DW" DW0016B-MFG -36.515,125.617 r0 top
U4 "TPD4E004DRYR" DRY0006A -33.654,113.379 r270 top
U5 "TPD4E004DRYR" DRY0006A -25.17,112.82 r0 top
U6 "TS5A23157DGSR" DGS0010A_N -33.679,98.523 r0 top
U7 "SN74LVC2G07DBVR" DBV0006A_N -17.983,94.922 r90 top
U8 "TS5A23157DGSR" DGS0010A_N -22.645,36.121 r180 top
U9 "TS5A23157DGSR" DGS0010A_N -25.398,97.899 r90 top
U10 "TPS3703A4330DSERQ1" DSE0006A -12.236,106.846 r0 bottom
U11 "SN74LV4053APWR" PW0016A-MFG -28.513,28.404 r180 top
U13 "SN74LVC8T245PW" PW0024A-MFG -29.294,14.652 r270 top locked
U15 "TCAN332GDR" D0008A_N -16.638,10.801 r270 top
U16 "TPD4E05U06DQAR" DQA0010A -45.598,129.866 r90 top
U17 "TS3A27518EPWR" PW0024A-MFG -43.206,78.363 r270 bottom locked
U18 "TPS61241YFFR" YFF0006AEAE -43.371,47.898 r0 top
U101 "TPS7A3701DRVR" DRV0006A -52.96,112.224 r180 top
USB101 "MUP-U22001" FP-MUP-U22001_CONN_USB_8MM94_8MM0-MFG -46.221,136.184 r180 top locked
Y1 "830064296" FP-830064296_SMT4_3MM4_2MM7-MFG -2.817,130.876 r90 top
Y2 "830108207209" FP-830108207209_SMT_CRYSTAL_3MM2_2MM5-MFG -15.261,56.778 r45 top
ZZ1 "These assemblies are ESD sensitive, ESD precautions shall be observed." AssemblyNote -52.979,147.69 r0 top
ZZ2 "These assemblies must be clean and free from flux and all contaminants. Use of no clean flux is not acceptable." AssemblyNote -52.808,151.398 r0 top
ZZ3 "These assemblies must comply with workmanship standards IPC-A-610 Class 2, unless otherwise specified." AssemblyNote -52.876,155.208 r0 top

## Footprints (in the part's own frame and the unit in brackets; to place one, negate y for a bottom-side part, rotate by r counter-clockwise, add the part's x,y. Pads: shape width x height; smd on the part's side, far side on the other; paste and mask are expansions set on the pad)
0402 [mm] "0402 from SM-752 data"
  rect 0.8x0.6 smd: 1(-0.6,0) 2(0.6,0)
  silkscreen extent -1.22,-0.52 1.22,0.52, body extent -0.55,-0.3 0.55,0.3, height 0.6
0603 [mm] "0603 from SM-752 data"
  rect 1x0.95 smd: 1(-0.8,0) 2(0.8,0)
  silkscreen extent -1.52,-0.69 1.52,0.69, body extent -0.87,-0.47 0.87,0.47, height 1
0805_HV [mil] "0805 with 30mil clearance between pads"
  rect 50x63 smd: 1(-40,0) 2(40,0)
  silkscreen extent -74,-40 74,40, body extent -43,-29 43,29, height 57
AssemblyNote [mm] "Assembly Note"
BoosterPack_40pin_J1J3 [mm] "Receptacle, 2.54mm, 10x2, TH"
  rrect6% 1.55x1.55 hole 1.02: 1(1.27,11.43)
  round 1.55 hole 1.02: 2(1.27,8.89) 3(1.27,6.35) 4(1.27,3.81) 5(1.27,1.27) 6(1.27,-1.27) 7(1.27,-3.81) 8(1.27,-6.35) 9(1.27,-8.89) 10(1.27,-11.43) 21(-1.27,11.43) 22(-1.27,8.89) 23(-1.27,6.35) 24(-1.27,3.81) 25(-1.27,1.27) 26(-1.27,-1.27) 27(-1.27,-3.81) 28(-1.27,-6.35) 29(-1.27,-8.89) 30(-1.27,-11.43)
  silkscreen extent -7.62,-12.95 7.62,12.95, body extent 0,0 0,0
BoosterPack_40pin_J2J4 [mm] "Receptacle, 2.54mm, 10x2, TH"
  round 1.55 hole 1.02: 11(-1.27,-11.43) 12(-1.27,-8.89) 13(-1.27,-6.35) 14(-1.27,-3.81) 15(-1.27,-1.27) 16(-1.27,1.27) 17(-1.27,3.81) 18(-1.27,6.35) 19(-1.27,8.89) 20(-1.27,11.43) 31(1.27,-11.43) 32(1.27,-8.89) 33(1.27,-6.35) 34(1.27,-3.81) 35(1.27,-1.27) 36(1.27,1.27) 37(1.27,3.81) 38(1.27,6.35) 39(1.27,8.89) 40(1.27,11.43)
  silkscreen extent -7.62,-12.95 2.48,12.95, body extent 0,0 0,0
BoosterPack_40pin_J5J7 [mm] "Receptacle, 2.54mm, 10x2, TH"
  round 1.55 hole 1.02: 41(1.27,11.43) 42(1.27,8.89) 43(1.27,6.35) 44(1.27,3.81) 45(1.27,1.27) 46(1.27,-1.27) 47(1.27,-3.81) 48(1.27,-6.35) 49(1.27,-8.89) 50(1.27,-11.43) 61(-1.27,11.43) 62(-1.27,8.89) 63(-1.27,6.35) 64(-1.27,3.81) 65(-1.27,1.27) 66(-1.27,-1.27) 67(-1.27,-3.81) 68(-1.27,-6.35) 69(-1.27,-8.89) 70(-1.27,-11.43)
  silkscreen extent -7.62,-12.95 7.62,12.95, body extent 0,0 0,0
BoosterPack_40pin_J6J8 [mm] "Receptacle, 2.54mm, 10x2, TH"
  round 1.55 hole 1.02: 51(-1.27,-11.43) 52(-1.27,-8.89) 53(-1.27,-6.35) 54(-1.27,-3.81) 55(-1.27,-1.27) 56(-1.27,1.27) 57(-1.27,3.81) 58(-1.27,6.35) 59(-1.27,8.89) 60(-1.27,11.43) 71(1.27,-11.43) 72(1.27,-8.89) 73(1.27,-6.35) 74(1.27,-3.81) 75(1.27,-1.27) 76(1.27,1.27) 77(1.27,3.81) 78(1.27,6.35) 79(1.27,8.89) 80(1.27,11.43)
  silkscreen extent -7.62,-12.95 2.48,12.95, body extent 0,0 0,0
CE_Mark_5mm [mm] "Minimum text height for CE Mark"
  silkscreen extent -3.5,-2.5 3.5,2.5
D0008A_N [mm] "SOIC, 8-Leads, Body 4.9x3.9mm, Pitch 1.27mm, IPC Medium Density"
  oval 1.45x0.6 smd: 1(-2.725,1.905) 2(-2.725,0.635) 3(-2.725,-0.635) 4(-2.725,-1.905) 5(2.725,-1.905) 6(2.725,-0.635) 7(2.725,0.635) 8(2.725,1.905)
  silkscreen extent -3.3,-2.5 0.9,2.5, body extent -3,-2.45 3,2.45, height 1.63
DBV0006A_N [mm] "SOT23, 6-Leads, Body 2.9x1.6mm, Pitch 0.95mm, Lead Span 2.8mm, IPC Medium Density"
  rrect17% 1x0.6 smd: 1(-1.375,0.95) 2(-1.375,0) 3(-1.375,-0.95) 4(1.375,-0.95) 5(1.375,0) 6(1.375,0.95)
  silkscreen extent -1.67,-1.55 0.5,1.55, body extent -1.42,-1.46 1.42,1.46, height 1.12
DGS0010A_N [mm] "TSSOP, 10-Leads, Body 3x3mm, Pitch 0.5mm, IPC Medium Density"
  oval 1.35x0.3 smd: 1(-2.225,1) 2(-2.225,0.5) 3(-2.225,0) 4(-2.225,-0.5) 5(-2.225,-1) 6(2.225,-1) 7(2.225,-0.5) 8(2.225,0) 9(2.225,0.5) 10(2.225,1)
  silkscreen extent -2.75,-1.55 0.9,1.55, body extent -2.45,-1.5 2.45,1.5, height 0.96
DQA0010A [mm] "SON, 10-Leads, Body 1x2.5mm, Pitch 0.5mm, TI Recommended"
  rrect50% 0.565x0.2 smd: 1(-0.417,1) 2(-0.418,0.5) 4(-0.418,-0.5) 5(-0.418,-1) 6(0.417,-1) 7(0.417,-0.5) 9(0.417,0.5) 10(0.417,1)
  rrect25% 0.565x0.4 smd: 3(-0.418,0) 8(0.417,0)
  rrect28% 0.565x0.36 on Top Paste: 3(-0.418,0) 8(0.417,0)
  silkscreen extent -0.67,-1.45 0.55,1.45, body extent -0.55,-1.3 0.55,1.3, height 0.56
DRV0006A [mm] "SON, 6-Leads, Body 2x2mm, Pitch 0.65mm, Thermal Pad 1.6x1mm, TI Recommended"
  rrect33% 0.45x0.3 smd: 1(-0.975,0.65) 2(-0.975,0) 3(-0.975,-0.65) 4(0.975,-0.65) 5(0.975,0) 6(0.975,0.65)
  rrect14% 1x0.7 on Top Paste: 7(0,0.45) 7(0,-0.45)
  rrect10% 1x1.6 smd: 7(0,0)
  silkscreen extent -1.05,-1.2 1.05,1.2, body extent -1.05,-1.05 1.05,1.05, height 0.81
DRY0006A [mm] "USON-6"
  rrect67% 0.45x0.3 smd: 1(-0.275,0.5)
  rrect67% 0.4x0.3 smd: 2(-0.3,0) 3(-0.3,-0.5) 4(0.3,-0.5) 5(0.3,0) 6(0.3,0.5)
  body extent -0.5,-0.72 0.5,0.73, height 0.58
DSE0006A [mm] "TI recommended land pattern"
  rect 0.66x0.25 smd: 1(-0.62,0.5)
  rect 0.7x0.25 smd: 2(-0.6,0) 3(-0.6,-0.5) 4(0.6,-0.5) 5(0.6,0) 6(0.6,0.5)
  Top Signal region: -0.3,0.625 -0.25,0.625 -0.15,0.525 -0.15,0.375 -0.3,0.375
  silkscreen extent -0.9,-0.92 0.9,0.92, body extent -0.77,-0.77 0.77,0.77, height 0.8
DW0016B-MFG [mm]
  rrect17% 1.65x0.6 smd: 1(-4.875,4.445) 2(-4.875,3.175) 3(-4.875,1.905) 4(-4.875,0.635) 5(-4.875,-0.635) 6(-4.875,-1.905) 7(-4.875,-3.175) 8(-4.875,-4.445) 9(4.875,-4.445) 10(4.875,-3.175) 11(4.875,-1.905) 12(4.875,-0.635) 13(4.875,0.635) 14(4.875,1.905) 15(4.875,3.175) 16(4.875,4.445)
  silkscreen extent -6.37,-5.25 3.5,5.25, body extent -5.8,-5.5 5.8,5.5, height 0.25
FCC_disclaimer [mm]
Fiducial10-20 [mm]
  round 1 smd mask+0.5: 1(0,0)
  Top Signal keep-out circle w1.178: c0,0 r0.5
FP-830064296_SMT4_3MM4_2MM7-MFG [mm]
  rrect9% 1.4x1.15 smd paste+0 mask+0: 1(-1.1,-0.8) 2(1.1,-0.8) 3(1.1,0.8) 4(-1.1,0.8)
  silkscreen extent -2.17,-2.05 2.17,1.35, body extent -1.9,-1.48 1.9,1.48, height 0.25
FP-61300421121_HDR4-MFG#1 [mm]
  rrect6% 1.7x1.7 hole 1.1: 1(-1.27,1.27)
  round 1.7 hole 1.1: 2(-1.27,-1.27) 3(1.27,1.27) 4(1.27,-1.27)
  silkscreen extent -2.69,-2.62 2.69,3.22, body extent -2.54,-2.54 2.54,2.54, height 8.89
FP-61300421121_HDR4-MFG#2 [mm]
  rrect6% 1.7x1.7 hole 1.1 paste-1000 mask+0: 1(-1.27,-1.27)
  round 1.7 hole 1.1 paste-1000 mask+0: 2(-1.27,1.27) 3(1.27,-1.27) 4(1.27,1.27)
  silkscreen extent -2.69,-3.22 2.69,2.62, body extent -2.79,-2.72 2.79,2.72, height 0.25
FP-61301221121_HDR12-MFG [mm]
  rrect6% 1.7x1.7 hole 1.1: 1(-6.35,-1.27)
  round 1.7 hole 1.1: 2(-6.35,1.27) 3(-3.81,-1.27) 4(-3.81,1.27) 5(-1.27,-1.27) 6(-1.27,1.27) 7(1.27,-1.27) 8(1.27,1.27) 9(3.81,-1.27) 10(3.81,1.27) 11(6.35,-1.27) 12(6.35,1.27)
  silkscreen extent -7.77,-3.22 7.77,2.62, body extent -7.87,-2.72 7.87,2.72, height 0.25
FP-830108207209_SMT_CRYSTAL_3MM2_2MM5-MFG [mm]
  rrect9% 1.4x1.15 smd paste+0 mask+0: 1(-1.1,-0.8) 2(1.1,-0.8) 3(1.1,0.8) 4(-1.1,0.8)
  silkscreen extent -1.22,-2.05 0,1.35, body extent -1.9,-1.47 1.9,1.47, height 0.25
FP-885012205018_0402-MFG [mm]
  rrect20% 0.5x0.5 smd paste+0 mask+0: 1(-0.5,0) 2(0.5,0)
  silkscreen extent -0.5,-0.63 0.5,0.63, body extent -0.85,-0.38 0.85,0.38, height 0.25
FP-885012205050_0402-MFG [mm]
  rrect20% 0.5x0.5 smd paste+0 mask+0: 1(-0.5,0) 2(0.5,0)
  silkscreen extent -0.53,-0.63 0.53,0.63, body extent -0.85,-0.38 0.85,0.38, height 0.25
FP-885012205064_0402-MFG [mm]
  rrect20% 0.5x0.5 smd paste+0 mask+0: 1(-0.5,0) 2(0.5,0)
  silkscreen extent -0.53,-0.63 0.53,0.63, body extent -0.85,-0.38 0.85,0.38, height 0.25
FP-CC0603KRX5R6BB106_0603-MFG [mm]
  rrect13% 0.8x0.9 smd paste+0 mask+0: 1(-0.75,0) 2(0.75,0)
  silkscreen extent -0.85,-0.88 0.85,0.88, body extent -0.8,-0.4 0.8,0.4, height 1
FP-FTSH-107-01-F-DV-K_HDR14-MFG [mm]
  rrect14% 0.74x2.79 smd: 1(-3.81,-2.035) 2(-3.81,2.035) 3(-2.54,-2.035) 4(-2.54,2.035) 5(-1.27,-2.035) 6(-1.27,2.035) 7(0,-2.035) 8(0,2.035) 9(1.27,-2.035) 10(1.27,2.035) 11(2.54,-2.035) 12(2.54,2.035) 13(3.81,-2.035) 14(3.81,2.035)
  silkscreen extent -4.51,-4.11 4.51,0.27, body extent -4.61,-3.53 4.61,3.53, height 0.25
FP-MUP-U22001_CONN_USB_8MM94_8MM0-MFG [mm]
  rrect100% 0.6x1.9 hole 1.9 slot 0.6 at 0 deg: 1(-4.32,3.35) 2(4.32,3.35)
  round 1.207 smd: 1(-4.25,2.92) 2(4.25,2.92)
  round 1.207 smd far side: 1(-4.25,2.92) 2(4.25,2.92)
  rrect100% 1.25x0.7 hole 0.7 slot 1.25 at 0 deg: 1(-3.995,2.75) 2(3.995,2.75)
  rrect100% 0.7x1.5 hole 1.5 slot 0.7 at 0 deg: 3(-5.85,-1.95) 4(5.85,-1.95)
  round 1.17 smd far side: 3(-5.85,-1.625) 4(5.85,-1.625)
  round 1.17 smd: 3(-5.85,-1.625) 4(5.85,-1.625)
  rrect37% 0.27x0.9 smd: A1(-2.625,4.05) A2(-2.125,4.05) A3(-1.625,4.05) A4(-1.125,4.05) A5(-0.625,4.05) A6(-0.125,4.05) A7(0.375,4.05) A8(0.875,4.05) A9(1.375,4.05) A10(1.875,4.05) A11(2.375,4.05) A12(2.875,4.05)
  rrect37% 0.27x0.8 smd: B1(2.625,2.45) B2(2.125,2.45) B3(1.625,2.45) B4(1.125,2.45) B5(0.625,2.45) B6(0.125,2.45) B7(-0.375,2.45) B8(-0.875,2.45) B9(-1.375,2.45) B10(-1.875,2.45) B11(-2.375,2.45) B12(-2.875,2.45)
  Top Signal region: 3.72,3.35 3.72,4.05 3.72,4.169 3.811,4.39 3.98,4.559 4.201,4.65 4.32,4.65 4.439,4.65 4.66,4.559 4.829,4.39 4.92,4.169 4.92,4.05 4.92,2.85 4.92,2.731 4.829,2.51 4.66,2.341 4.439,2.25 4.32,2.25 3.82,2.25 3.711,2.25 3.508,2.334 3.354,2.488 3.27,2.691 3.27,2.8 3.268,2.898 3.332,3.082 3.456,3.233 3.624,3.332
  Top Signal region: 6.5,-2.349 6.5,-2.472 6.411,-2.701 6.244,-2.882 6.023,-2.99 5.9,-2.999 5.833,-3.004 5.699,-2.987 5.572,-2.942 5.457,-2.873 5.358,-2.781 5.281,-2.672 5.227,-2.548 5.2,-2.416 5.2,-2.349 5.2,-0.749 5.2,-0.65 5.276,-0.466 5.417,-0.325 5.601,-0.249 5.7,-0.249 6,-0.249 6.099,-0.249 6.283,-0.325 6.424,-0.466 6.5,-0.65 6.5,-0.749
  Top Signal region: -3.72,3.35 -3.72,4.05 -3.72,4.169 -3.811,4.39 -3.98,4.559 -4.201,4.65 -4.439,4.65 -4.66,4.559 -4.829,4.39 -4.92,4.169 -4.92,4.05 -4.92,2.85 -4.92,2.731 -4.829,2.51 -4.66,2.341 -4.439,2.25 -4.32,2.25 -3.711,2.25 -3.508,2.334 -3.354,2.488 -3.27,2.691 -3.27,2.8 -3.268,2.898 -3.332,3.082 -3.456,3.233 -3.624,3.332
  Top Signal region: -6.5,-2.349 -6.5,-2.472 -6.411,-2.701 -6.244,-2.882 -6.023,-2.99 -5.9,-2.999 -5.833,-3.004 -5.699,-2.987 -5.572,-2.942 -5.457,-2.873 -5.358,-2.781 -5.281,-2.672 -5.227,-2.548 -5.2,-2.416 -5.2,-2.349 -5.2,-0.749 -5.2,-0.65 -5.276,-0.466 -5.417,-0.325 -5.601,-0.249 -5.7,-0.249 -6,-0.249 -6.099,-0.249 -6.283,-0.325 -6.424,-0.466 -6.5,-0.65 -6.5,-0.749
  Bottom Signal region: 3.72,3.35 3.72,4.05 3.72,4.169 3.811,4.39 3.98,4.559 4.201,4.65 4.32,4.65 4.439,4.65 4.66,4.559 4.829,4.39 4.92,4.169 4.92,4.05 4.92,2.85 4.92,2.731 4.829,2.51 4.66,2.341 4.439,2.25 4.32,2.25 3.82,2.25 3.711,2.25 3.508,2.334 3.354,2.488 3.27,2.691 3.27,2.8 3.268,2.898 3.332,3.082 3.456,3.233 3.624,3.332
  Bottom Signal region: -3.72,3.35 -3.72,4.05 -3.72,4.169 -3.811,4.39 -3.98,4.559 -4.201,4.65 -4.32,4.65 -4.439,4.65 -4.66,4.559 -4.829,4.39 -4.92,4.169 -4.92,4.05 -4.92,2.85 -4.92,2.731 -4.829,2.51 -4.66,2.341 -4.439,2.25 -4.32,2.25 -3.82,2.25 -3.711,2.25 -3.508,2.334 -3.354,2.488 -3.27,2.691 -3.27,2.8 -3.268,2.898 -3.332,3.082 -3.456,3.233 -3.624,3.332
  Bottom Signal region: 6.5,-2.349 6.5,-2.472 6.411,-2.701 6.244,-2.882 6.023,-2.99 5.9,-2.999 5.833,-3.004 5.699,-2.987 5.572,-2.942 5.457,-2.873 5.358,-2.781 5.281,-2.672 5.227,-2.548 5.2,-2.416 5.2,-2.349 5.2,-0.749 5.2,-0.65 5.276,-0.466 5.417,-0.325 5.601,-0.249 5.7,-0.249 6,-0.249 6.099,-0.249 6.283,-0.325 6.424,-0.466 6.5,-0.65 6.5,-0.749
  Bottom Signal region: -6.5,-2.349 -6.5,-2.472 -6.411,-2.701 -6.244,-2.882 -6.023,-2.99 -5.9,-2.999 -5.833,-3.004 -5.699,-2.987 -5.572,-2.942 -5.457,-2.873 -5.358,-2.781 -5.281,-2.672 -5.227,-2.548 -5.2,-2.416 -5.2,-2.349 -5.2,-0.749 -5.2,-0.65 -5.276,-0.466 -5.417,-0.325 -5.601,-0.249 -5.7,-0.249 -6,-0.249 -6.099,-0.249 -6.283,-0.325 -6.424,-0.466 -6.5,-0.65 -6.5,-0.749
  Keep-Out Layer lines w0.2: 4.7,-3.5 4.7,0.75 ccw(c4.7,1.25) 5.2,1.25 ccw(c4.7,1.25) 4.7,1.75 -4.7,1.75 ccw(c-4.7,1.25) -5.2,1.25 ccw(c-4.7,1.25) -4.7,0.75 -4.7,-3.5
  silkscreen extent -6,0.13 6,5.17, body extent -6.6,-4.23 6.6,4.75, height 0.25
FP-TSW-103-07-G-T_HDR9-MFG [mm]
  rrect6% 1.57x1.57 hole 1.02 paste-1000 mask+0: 1(-2.54,-2.54)
  round 1.57 hole 1.02 paste-1000 mask+0: 2(-2.54,0) 3(-2.54,2.54) 4(0,-2.54) 5(0,0) 6(0,2.54) 7(2.54,-2.54) 8(2.54,0) 9(2.54,2.54)
  silkscreen extent -4.66,-3.88 3.94,3.88, body extent -4.04,-3.98 4.04,3.98, height 0.25
LED_LTST-C171 [mm] "LITE-ON"
  rect 1.2x1.2 smd: 1(-1.05,0) 2(1.05,0)
  silkscreen extent -1.6,-1 2.2,1, body extent -1.05,-0.67 1.05,0.67, height 0.8
LTST-C170TBKT_Blue [mm] "LITE-ON"
  rect 1.2x1.2 smd: 1(-1.05,0) 2(1.05,0)
  silkscreen extent -1.6,-1 2.2,1, body extent -1.05,-0.67 1.05,0.67, height 1.2
NPTH125mil [mil]
  round 120 hole 125 unplated: 1(0,0)
PDT0128A [mm] "Thin QFP, 128-Leads, Body 14x14mm, Pitch 0.4mm"
  oval 1.4x0.2 smd: 1(-7.7,6.2) 2(-7.7,5.8) 3(-7.7,5.4) 4(-7.7,5) 5(-7.7,4.6) 6(-7.7,4.2) 7(-7.7,3.8) 8(-7.7,3.4) 9(-7.7,3) 10(-7.7,2.6) 11(-7.7,2.2) 12(-7.7,1.8) 13(-7.7,1.4) 14(-7.7,1) 15(-7.7,0.6) 16(-7.7,0.2) 17(-7.7,-0.2) 18(-7.7,-0.6) 19(-7.7,-1) 20(-7.7,-1.4) 21(-7.7,-1.8) 22(-7.7,-2.2) 23(-7.7,-2.6) 24(-7.7,-3) 25(-7.7,-3.4) 26(-7.7,-3.8) 27(-7.7,-4.2) 28(-7.7,-4.6) 29(-7.7,-5) 30(-7.7,-5.4) 31(-7.7,-5.8) 32(-7.7,-6.2) 65(7.7,-6.2) 66(7.7,-5.8) 67(7.7,-5.4) 68(7.7,-5) 69(7.7,-4.6) 70(7.7,-4.2) 71(7.7,-3.8) 72(7.7,-3.4) 73(7.7,-3) 74(7.7,-2.6) 75(7.7,-2.2) 76(7.7,-1.8) 77(7.7,-1.4) 78(7.7,-1) 79(7.7,-0.6) 80(7.7,-0.2) 81(7.7,0.2) 82(7.7,0.6) 83(7.7,1) 84(7.7,1.4) 85(7.7,1.8) 86(7.7,2.2) 87(7.7,2.6) 88(7.7,3) 89(7.7,3.4) 90(7.7,3.8) 91(7.7,4.2) 92(7.7,4.6) 93(7.7,5) 94(7.7,5.4) 95(7.7,5.8) 96(7.7,6.2)
  oval 0.2x1.4 smd: 33(-6.2,-7.7) 34(-5.8,-7.7) 35(-5.4,-7.7) 36(-5,-7.7) 37(-4.6,-7.7) 38(-4.2,-7.7) 39(-3.8,-7.7) 40(-3.4,-7.7) 41(-3,-7.7) 42(-2.6,-7.7) 43(-2.2,-7.7) 44(-1.8,-7.7) 45(-1.4,-7.7) 46(-1,-7.7) 47(-0.6,-7.7) 48(-0.2,-7.7) 49(0.2,-7.7) 50(0.6,-7.7) 51(1,-7.7) 52(1.4,-7.7) 53(1.8,-7.7) 54(2.2,-7.7) 55(2.6,-7.7) 56(3,-7.7) 57(3.4,-7.7) 58(3.8,-7.7) 59(4.2,-7.7) 60(4.6,-7.7) 61(5,-7.7) 62(5.4,-7.7) 63(5.8,-7.7) 64(6.2,-7.7) 97(6.2,7.7) 98(5.8,7.7) 99(5.4,7.7) 100(5,7.7) 101(4.6,7.7) 102(4.2,7.7) 103(3.8,7.7) 104(3.4,7.7) 105(3,7.7) 106(2.6,7.7) 107(2.2,7.7) 108(1.8,7.7) 109(1.4,7.7) 110(1,7.7) 111(0.6,7.7) 112(0.2,7.7) 113(-0.2,7.7) 114(-0.6,7.7) 115(-1,7.7) 116(-1.4,7.7) 117(-1.8,7.7) 118(-2.2,7.7) 119(-2.6,7.7) 120(-3,7.7) 121(-3.4,7.7) 122(-3.8,7.7) 123(-4.2,7.7) 124(-4.6,7.7) 125(-5,7.7) 126(-5.4,7.7) 127(-5.8,7.7) 128(-6.2,7.7)
  silkscreen extent -7.7,-6.3 6.3,6.99, body extent -8,-8 8,8, height 1.07
PW0016A-MFG [mm]
  rrect22% 1.5x0.45 smd: 1(-2.9,2.275) 2(-2.9,1.625) 3(-2.9,0.975) 4(-2.9,0.325) 5(-2.9,-0.325) 6(-2.9,-0.975) 7(-2.9,-1.625) 8(-2.9,-2.275) 9(2.9,-2.275) 10(2.9,-1.625) 11(2.9,-0.975) 12(2.9,-0.325) 13(2.9,0.325) 14(2.9,0.975) 15(2.9,1.625) 16(2.9,2.275)
  silkscreen extent -4.38,-2.55 1.78,2.55, body extent -3.75,-2.8 3.75,2.8, height 0.25
PW0024A-MFG [mm]
  rrect22% 1.5x0.45 smd paste+0 mask+0: 1(-2.9,3.575) 2(-2.9,2.925) 3(-2.9,2.275) 4(-2.9,1.625) 5(-2.9,0.975) 6(-2.9,0.325) 7(-2.9,-0.325) 8(-2.9,-0.975) 9(-2.9,-1.625) 10(-2.9,-2.275) 11(-2.9,-2.925) 12(-2.9,-3.575) 13(2.9,-3.575) 14(2.9,-2.925) 15(2.9,-2.275) 16(2.9,-1.625) 17(2.9,-0.975) 18(2.9,-0.325) 19(2.9,0.325) 20(2.9,0.975) 21(2.9,1.625) 22(2.9,2.275) 23(2.9,2.925) 24(2.9,3.575)
  silkscreen extent -4.32,-3.95 1.78,3.95, body extent -3.75,-4.2 3.75,4.2, height 0.25
PZ0100A-MFG [mm]
  rrect33% 1.6x0.3 smd paste-1000 mask+0: 1(-7.6,6) 2(-7.6,5.5) 3(-7.6,5) 4(-7.6,4.5) 5(-7.6,4) 6(-7.6,3.5) 7(-7.6,3) 8(-7.6,2.5) 9(-7.6,2) 10(-7.6,1.5) 11(-7.6,1) 12(-7.6,0.5) 13(-7.6,0) 14(-7.6,-0.5) 15(-7.6,-1) 16(-7.6,-1.5) 17(-7.6,-2) 18(-7.6,-2.5) 19(-7.6,-3) 20(-7.6,-3.5) 21(-7.6,-4) 22(-7.6,-4.5) 23(-7.6,-5) 24(-7.6,-5.5) 25(-7.6,-6) 51(7.6,-6) 52(7.6,-5.5) 53(7.6,-5) 54(7.6,-4.5) 55(7.6,-4) 56(7.6,-3.5) 57(7.6,-3) 58(7.6,-2.5) 59(7.6,-2) 60(7.6,-1.5) 61(7.6,-1) 62(7.6,-0.5) 63(7.6,0) 64(7.6,0.5) 65(7.6,1) 66(7.6,1.5) 67(7.6,2) 68(7.6,2.5) 69(7.6,3) 70(7.6,3.5) 71(7.6,4) 72(7.6,4.5) 73(7.6,5) 74(7.6,5.5) 75(7.6,6)
  rrect33% 0.3x1.6 smd paste-1000 mask+0: 26(-6,-7.6) 27(-5.5,-7.6) 28(-5,-7.6) 29(-4.5,-7.6) 30(-4,-7.6) 31(-3.5,-7.6) 32(-3,-7.6) 33(-2.5,-7.6) 34(-2,-7.6) 35(-1.5,-7.6) 36(-1,-7.6) 37(-0.5,-7.6) 38(0,-7.6) 39(0.5,-7.6) 40(1,-7.6) 41(1.5,-7.6) 42(2,-7.6) 43(2.5,-7.6) 44(3,-7.6) 45(3.5,-7.6) 46(4,-7.6) 47(4.5,-7.6) 48(5,-7.6) 49(5.5,-7.6) 50(6,-7.6) 76(6,7.6) 77(5.5,7.6) 78(5,7.6) 79(4.5,7.6) 80(4,7.6) 81(3.5,7.6) 82(3,7.6) 83(2.5,7.6) 84(2,7.6) 85(1.5,7.6) 86(1,7.6) 87(0.5,7.6) 88(0,7.6) 89(-0.5,7.6) 90(-1,7.6) 91(-1.5,7.6) 92(-2,7.6) 93(-2.5,7.6) 94(-3,7.6) 95(-3.5,7.6) 96(-4,7.6) 97(-4.5,7.6) 98(-5,7.6) 99(-5.5,7.6) 100(-6,7.6)
  silkscreen extent -9.12,-7.1 7.1,7.1, body extent -8.5,-8.5 8.5,8.5, height 0.25
Samtec_TSM-102-01-x-DV [mm] "Header, 2.54mm, 2x2, SMT"
  rect 3.048x1.27 smd: 1(-2.475,-1.27) 2(2.475,-1.27) 3(-2.475,1.27) 4(2.475,1.27)
  silkscreen extent -1.75,-2.63 1.65,2.54, body extent -3.85,-2.54 3.85,2.54, height 9.65
SW_1188E [mm] "SMD, 4-Leads, Body 7.8x3.5mm"
  rrect10% 1x1.45 smd: 1(-1.1,3.375) 2(-1.1,-3.375)
  rrect11% 1.3x0.9 smd: 3(0.7,2.1) 4(0.7,-2.1)
  round 0 hole 0.9 unplated: ""(-0.35,1.15) ""(-0.35,-1.15)
  silkscreen extent -1.98,-2.28 0.95,2.28, body extent -2.55,-3.9 1.05,3.9, height 3.5
SW_CAS-120TA [mm] "COPAL ELECTRONICS"
  rect 1.6x1 smd: 1(-1.15,1.75) 2(1.15,0) 3(-1.15,-1.75)
  silkscreen extent -2,-2.85 1.4,2.92, body extent -1.4,-2.85 1.4,2.85, height 2.51
SW_CAS-220TA [mm] "COPAL ELECTRONICS"
  rect 1.6x1 smd: 1(-1.85,1.75) 2(-1.85,0) 3(-1.85,-1.75) 4(1.85,1.75) 5(1.85,0) 6(1.85,-1.75)
  silkscreen extent -2.11,-2.9 2,3.58, body extent -2.1,-2.85 2.1,2.85, height 2.51
SW_CAS-D20TA [mm] "SMD, 6-Leads, Body 5.4x3.9mm, Pitch 1.75mm"
  rect 1.6x1 smd: 1(-1.85,1.75) 2(-1.85,0) 3(-1.85,-1.75) 4(1.85,1.75) 5(1.85,0) 6(1.85,-1.75)
  silkscreen extent -1.95,-2.7 1.95,2.9, body extent -2.1,-2.7 2.1,2.7, height 2.5
TI_Stacked_Overlay_Medium [mm]
  silkscreen extent -14.62,-3.44 14.62,3.42
TI_Symbol_Overlay_Small [mm]
  silkscreen extent -2.3,-2.23 2.3,2.24
TP_50MIL-25MILHOLE [mm]
  round 1.27 hole 0.635: 1(0,0)
WEEE_Minimum [mm] "WEEElie bin"
  silkscreen extent -2.42,-4.38 2.52,2.65
WL-SMCW_RED_0805 [mm] "SMD, 2-Leads, Body 1.6x0.8mm"
  rect 1.1x1.2 smd: 1(-1.05,0) 2(1.05,0)
  silkscreen extent -2.4,-1.1 1.5,1.1, body extent -1,-0.62 1,0.63, height 0.7
Wurth_60900213421 [mil] "Shunt, 2.54mm, Black"
  round 1 on Mech3: 0(0,0)
  body extent -98,-48 98,48, height 338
